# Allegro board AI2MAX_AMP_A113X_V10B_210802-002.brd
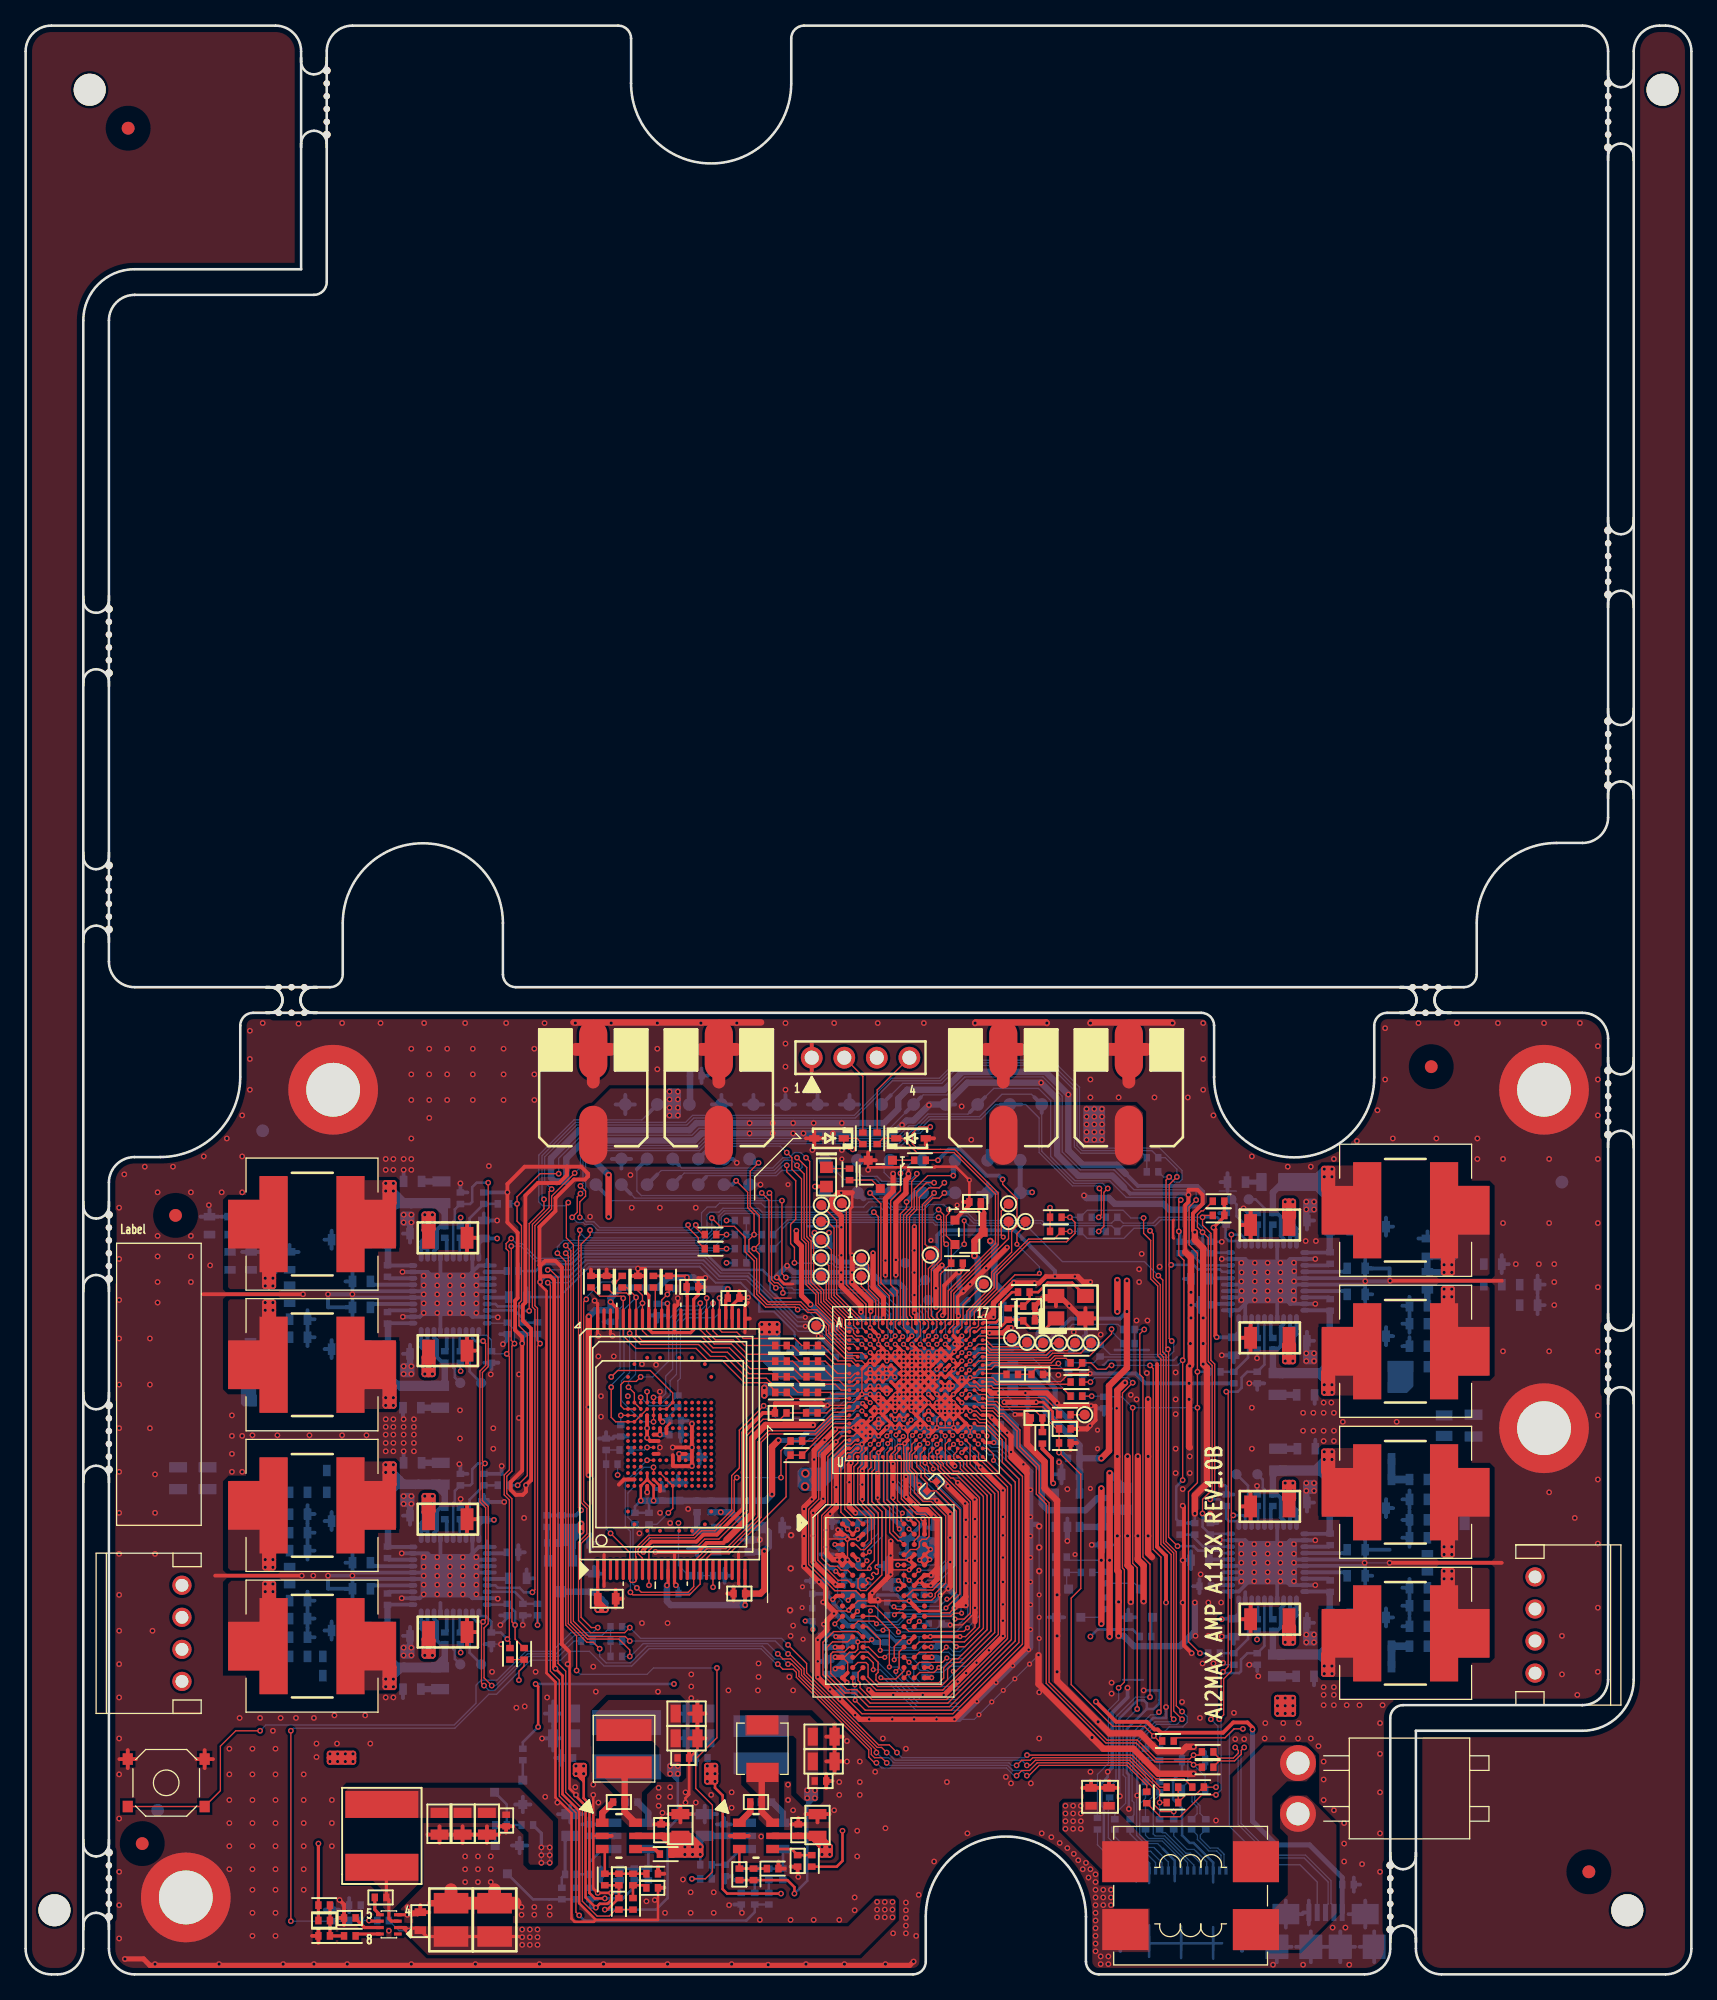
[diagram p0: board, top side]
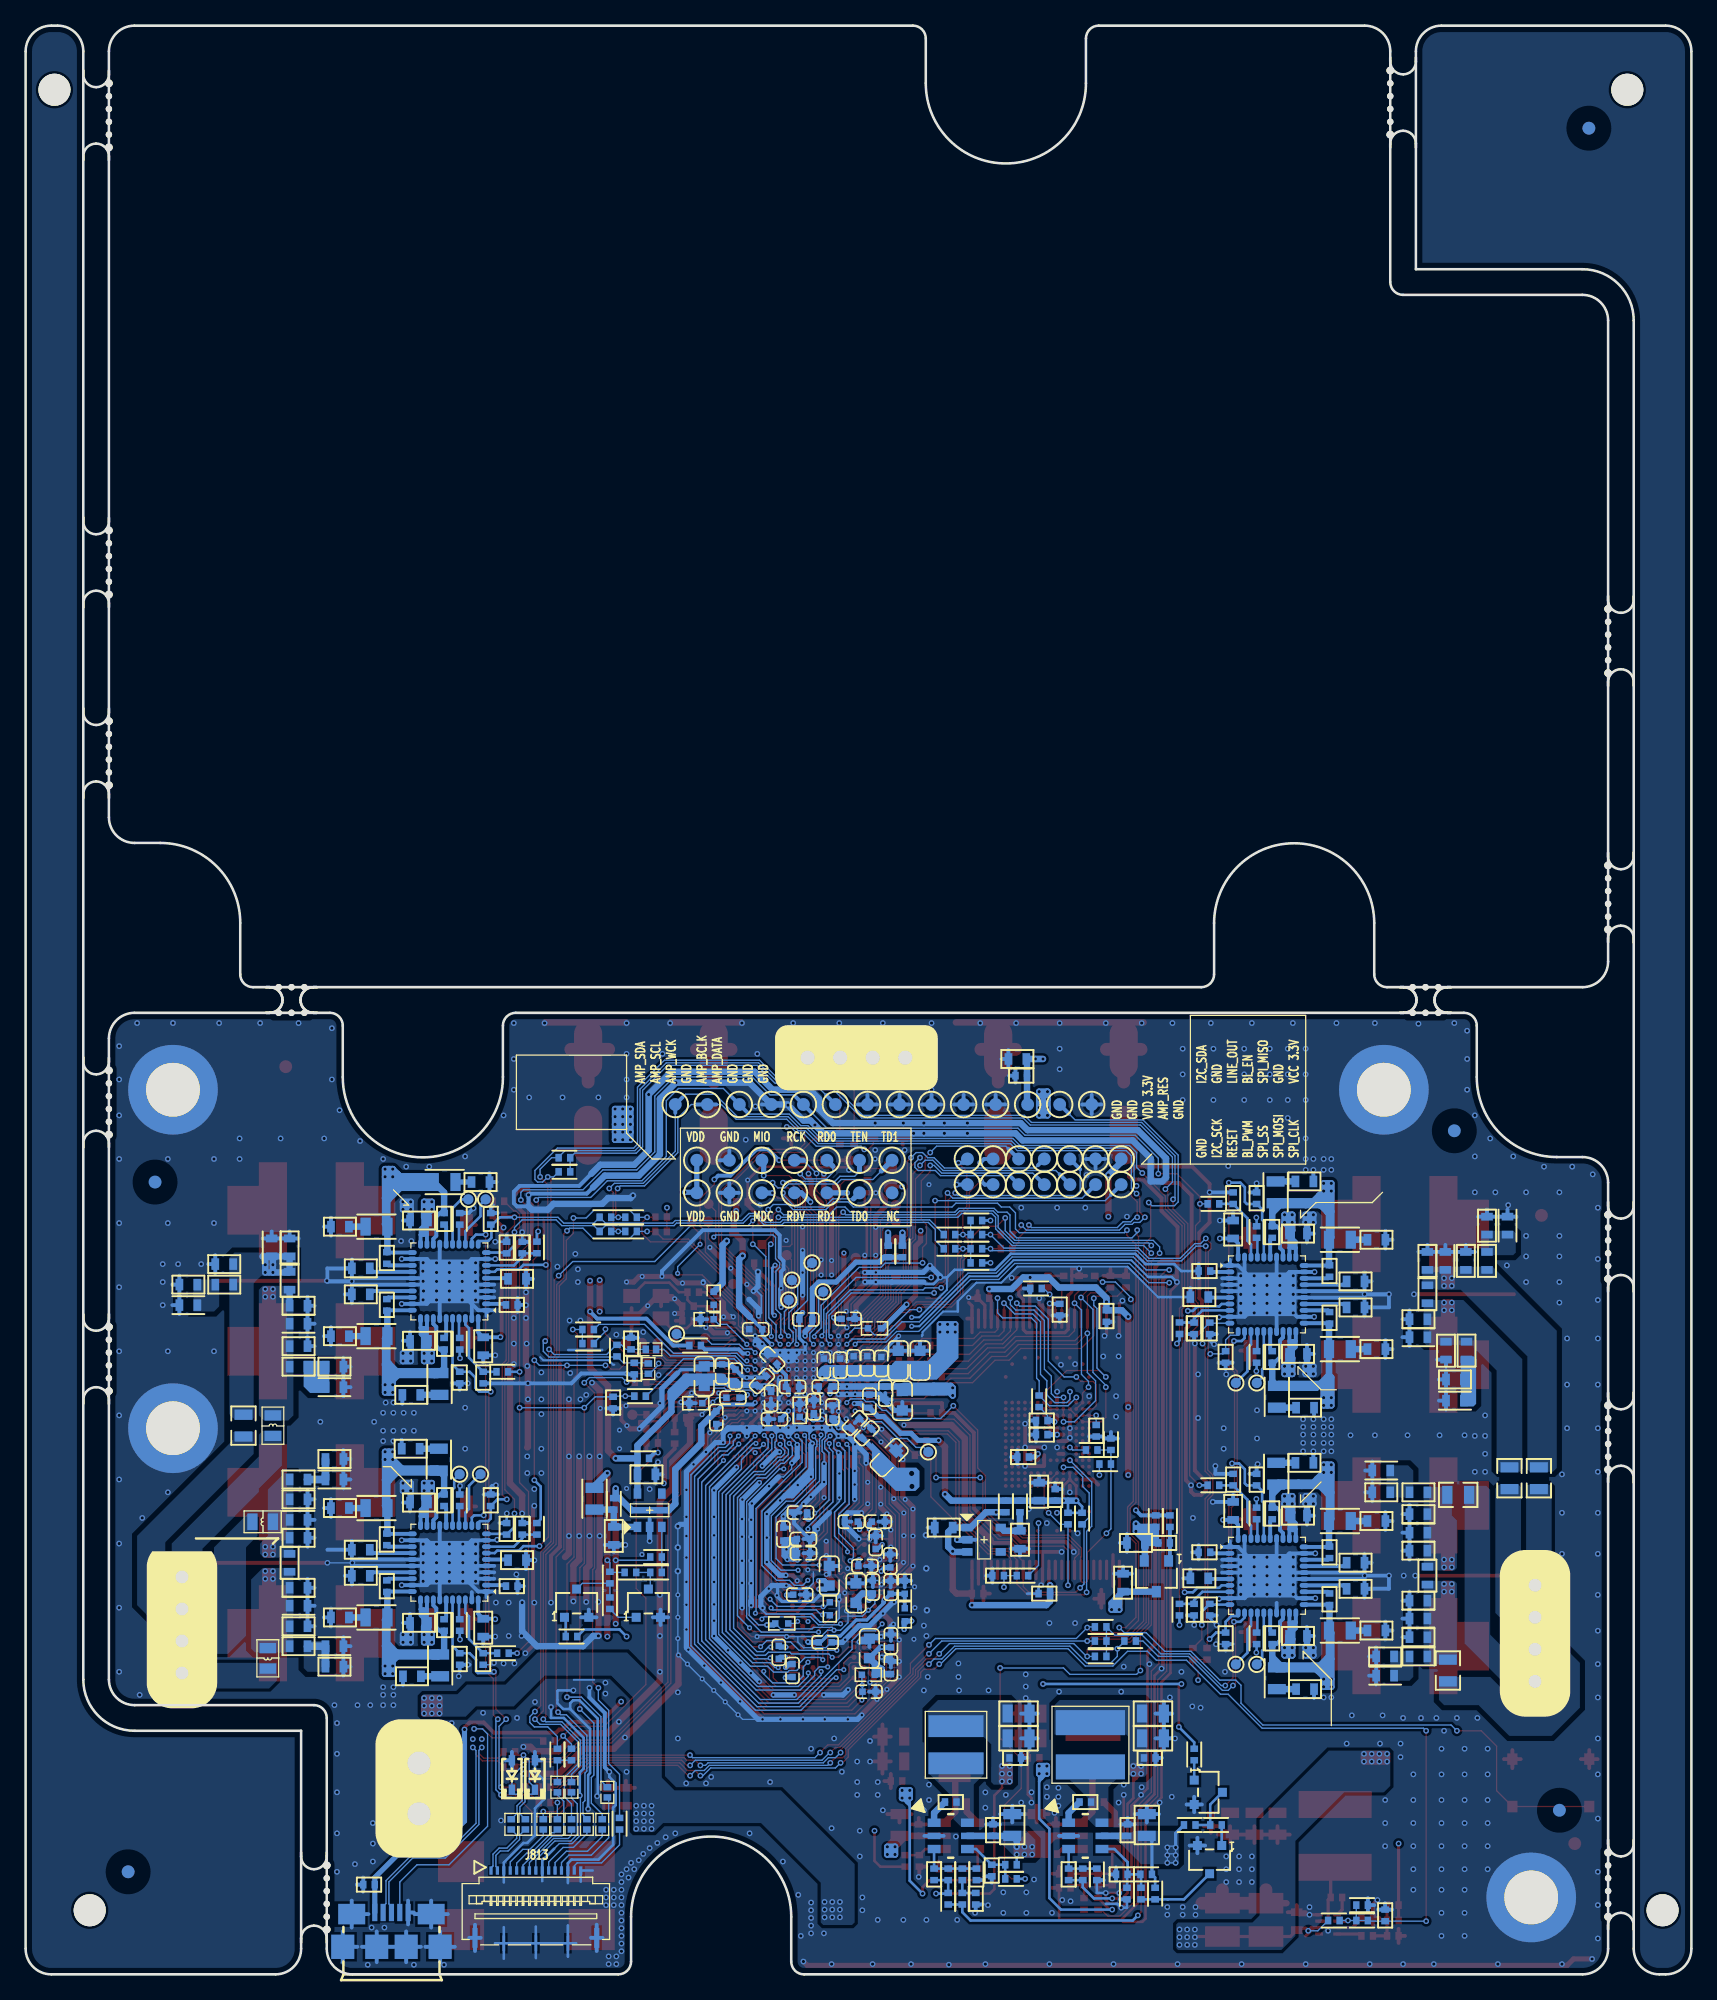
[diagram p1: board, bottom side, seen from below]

Outline 130 x 152 mm; copper layers: TOP, MID1(L2), MID2(L3), BOTTOM. Coordinates in mm from the lower left corner of the outline.
Outline path: 0,150 0,2 arc(0.59,0.59) 2,0 2.5,0 arc(3.91,0.59) 4.5,2 4.5,129 arc(5.67,131.83) 8.5,133 21.5,133 21.5,150 arc(20.91,151.41) 19.5,152 2,152 arc(0.59,151.41) 0,150 ; 6.5,129 6.5,79 arc(7.09,77.59) 8.5,77 23.75,77 arc(24.46,77.29) 24.75,78 24.75,82 arc(31,88.25) 37.25,82 37.25,78 arc(37.54,77.29) 38.25,77 112.25,77 arc(112.96,77.29) 113.25,78 113.25,82 arc(115.08,86.42) 119.5,88.25 121.5,88.25 arc(122.91,88.84) 123.5,90.25 123.5,150 arc(122.91,151.41) 121.5,152 60.75,152 arc(60.04,151.71) 59.75,151 59.75,147.5 arc(53.5,141.25) 47.25,147.5 47.25,151 arc(46.96,151.71) 46.25,152 25.5,152 arc(24.09,151.41) 23.5,150 23.5,132 arc(23.21,131.29) 22.5,131 8.5,131 arc(7.09,130.41) 6.5,129 ; 6.5,61.75 6.5,2 arc(7.09,0.59) 8.5,0 69.25,0 arc(69.96,0.29) 70.25,1 70.25,4.5 arc(76.5,10.75) 82.75,4.5 82.75,1 arc(83.04,0.29) 83.75,0 104.5,0 arc(105.91,0.59) 106.5,2 106.5,20 arc(106.79,20.71) 107.5,21 121.5,21 arc(122.91,21.59) 123.5,23 123.5,73 arc(122.91,74.41) 121.5,75 106.25,75 arc(105.54,74.71) 105.25,74 105.25,70 arc(99,63.75) 92.75,70 92.75,74 arc(92.46,74.71) 91.75,75 17.75,75 arc(17.04,74.71) 16.75,74 16.75,70 arc(14.92,65.58) 10.5,63.75 8.5,63.75 arc(7.09,63.16) 6.5,61.75 ; 108.5,19 108.5,2 arc(109.09,0.59) 110.5,0 128,0 arc(129.41,0.59) 130,2 130,150 arc(129.41,151.41) 128,152 127.5,152 arc(126.09,151.41) 125.5,150 125.5,23 arc(124.33,20.17) 121.5,19 108.5,19

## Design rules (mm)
net group I2S1: nets BCLK DATA LRCK
net group POWER: nets N21714583 N21714673 N21714779 N21715058 N21715192 N21715315 N21715441 N21715523 N21715623 N21715900 N21716032 N21716155 N21722582 N21722669 N21722769 N21723040 N21723161 N21723285 N21723494 N21723601 N21723713 N21724007 N21727322 N21727332
net group USBOTG_A_DM: nets N21775203 N22017810 USBOTG_A_DM
net group USBOTG_A_DP: nets N21775223 N22060831 USBOTG_A_DP

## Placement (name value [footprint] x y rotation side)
C1  105P/50V/1608  [C1608]  84.55 13.85 90 top
C2  104P/50V/1608  [C1608]  83.15 13.85 90 top
C3  106P/50V/3225  [C3225]  36.6 4.25 90 top
C4  104P/50V/1608  [C1608]  30.8 4.15 90 top
C5  104P/16V/1005  [C1005]  27.7 6 0 top
C6  226P/10V/2012  [C2012]  32.3 11.75 270 top
C7  226P/10V/2012  [C2012]  34.1 11.75 270 top
C8  OPEN-226P/10V/2012  [C2012]  36 11.75 270 top
C9  104P/16V/1005  [C1005]  37.5 12 90 top
C10  470P/50V/1005  [C1005]  23.3 4.2 180 top
C11  223P/50V/1005  [C1005]  25.3 4.4 0 top
C12  OPEN-104P/16V/1005  [C1005]  23.9 4.6 270 bottom
C13  226P/10V/2012  [C2012]  42.5 11.65 90 bottom
C14  104P/16V/1005  [C1005]  44 11.25 270 bottom
C15  104P/16V/1005  [C1005]  47.3 13.44 180 bottom
C16  226P/6.3V/2012  [C2012]  42.02 20.34 180 bottom
C17  104P/16V/1005  [C1005]  42.27 16.88 0 bottom
C18  226P/6.3V/2012  [C2012]  42.02 18.41 180 bottom
C19  330P/50V/1005  [C1005]  48.6 7.8 270 bottom
C20  104P/16V/1005  [C1005]  44.45 7.8 180 bottom
C21  106P/6.3V/1608  [C1608]  43.35 33.65 0 bottom
C22  106P/6.3V/1608  [C1608]  44.35 30.55 90 bottom
C23  104P/16V/1005  [C1005]  41.15 33.65 0 bottom
C30  106P/50V/3225  [C3225]  33.2 4.25 90 top
C51  226P/10V/2012  [C2012]  53 11.65 90 bottom
C52  104P/16V/1005  [C1005]  54.5 11.25 270 bottom
C53  104P/16V/1005  [C1005]  57.8 13.44 180 bottom
C54  226P/6.3V/2012  [C2012]  52.51 20.34 180 bottom
C55  104P/16V/1005  [C1005]  52.77 16.88 0 bottom
C56  226P/6.3V/2012  [C2012]  52.51 18.41 180 bottom
C57  226P/10V/2012  [C2012]  51.1 11.65 90 top
C58  104P/16V/1005  [C1005]  49.6 11.25 270 top
C59  104P/16V/1005  [C1005]  46.3 13.44 0 top
C60  226P/6.3V/2012  [C2012]  51.58 20.34 0 top
C61  104P/16V/1005  [C1005]  51.33 16.88 180 top
C62  226P/6.3V/2012  [C2012]  51.58 18.41 0 top
C63  270P/50V/1005  [C1005]  59.1 7.8 270 bottom
C64  270P/50V/1005  [C1005]  46.3 7.4 270 top
C65  104P/16V/1005  [C1005]  54.6 8.1 90 bottom
C66  102P/16V/1005  [C1005]  55.85 5.9 90 bottom
C67  102P/16V/1005  [C1005]  48.9 6.75 180 top
C68  226P/10V/2012  [C2012]  61.8 11.65 90 top
C69  104P/16V/1005  [C1005]  60.3 11.25 270 top
C70  104P/16V/1005  [C1005]  57 13.44 0 top
C71  226P/6.3V/2012  [C2012]  62.28 18.54 0 top
C72  104P/16V/1005  [C1005]  62.03 15.08 180 top
C73  226P/6.3V/2012  [C2012]  62.28 16.61 0 top
C74  330P/50V/1005  [C1005]  55.7 7.8 270 top
C75  OPEN-104P/16V/1005  [C1005]  60.25 8.85 90 top
C76  106P/6.3V/1608  [C1608]  81.55 39 180 bottom
C77  OPEN-106P/6.3V/1608  [C1608]  52.4 33.9 270 bottom
C78  472P/50V/1608  [C1608]  84.1 34.2 270 bottom
C79  OPEN-472P/50V/1608  [C1608]  58.35 34.85 0 bottom
C101  104P/16V/1005  [C0402]  76.1 43.43 90 bottom
C102  105P/6.3V/1005  [C0402]  69.11 51.08 180 bottom
C103  OPEN-150P/50V/1005  [C1005]  84.15 44.6 90 bottom
C104  OPEN-150P/50V/1005  [C1005]  78.95 46.8 180 top
C105  OPEN-150P/50V/1005  [C1005]  82.5 47.25 90 bottom
C106  OPEN-150P/50V/1005  [C1005]  82.75 49.2 270 bottom
C201  105P/6.3V/1608  [C1608]  94.29 48.99 270 bottom
C202  223P/16V/1005  [C1005]  97.34 49.19 270 bottom
C203  271P/50V/1608  [C1608]  99.9 45.2 180 bottom
C204  104P/16V/1005  [C1005]  96.12 46.55 90 bottom
C205  100uF/35V/CLZ  [ECAP_8PI_H10]  54.1 68.8 270 top
C206  104P/50V/1608  [C1608]  99.3 49.42 0 bottom
C207  271P/50V/1608  [C1608]  105.47 49.78 180 bottom
C208  OPEN-104P/16V/1005  [C1005]  92.06 52.22 0 bottom
C209  105P/50V/1608  [C1608]  108.7 52.15 180 bottom
C210  223P/16V/1005  [C1005]  101.81 52.22 90 bottom
C211  105P/16V/1608  [C1608]  103.84 53.04 0 bottom
C213  471P/50V/1608  [C1608]  109.4 54.1 90 bottom
C214  105P/16V/1608  [C1608]  103.84 55.07 0 bottom
C215  223P/16V/1005  [C1005]  101.81 55.88 270 bottom
C216  105P/50V/1608  [C1608]  109.4 56.7 270 bottom
C217  330P/50V/1005  [C1005]  92.46 56.69 270 bottom
C218  105P/6.3V/1608  [C1608]  91.65 54.25 180 bottom
C219  271P/50V/1608  [C1608]  105.47 58.32 180 bottom
C220  223P/16V/1005  [C1005]  97.34 58.93 270 bottom
C221  271P/50V/1608  [C1608]  94.5 61.8 0 bottom
C222  330P/50V/1005  [C1005]  93.7 58.93 270 bottom
C223  100uF/35V/CLZ  [ECAP_8PI_H10]  44.3 68.8 270 top
C224  104P/50V/1608  [C1608]  99.3 58.8 0 bottom
C225  223P/16V/1005  [C1005]  97.34 27.25 270 bottom
C226  104P/16V/1005  [C1005]  96.12 24.6 90 bottom
C228  271P/50V/1608  [C1608]  99.85 23.25 180 bottom
C229  271P/50V/1608  [C1608]  105.47 27.84 180 bottom
C230  105P/6.3V/1608  [C1608]  94.29 27.04 270 bottom
C231  104P/50V/1608  [C1608]  99.3 27.42 0 bottom
C232  OPEN-104P/16V/1005  [C1005]  92.06 30.28 0 bottom
C233  105P/50V/1608  [C1608]  108.7 30.15 180 bottom
C234  223P/16V/1005  [C1005]  101.81 30.28 90 bottom
C235  105P/16V/1608  [C1608]  103.84 31.09 0 bottom
C237  471P/50V/1608  [C1608]  109.4 32.1 90 bottom
C238  105P/16V/1608  [C1608]  103.84 33.12 0 bottom
C239  223P/16V/1005  [C1005]  101.81 33.93 270 bottom
C240  105P/50V/1608  [C1608]  108.7 34.05 0 bottom
C241  330P/50V/1005  [C1005]  92.46 34.75 270 bottom
C242  105P/6.3V/1608  [C1608]  91.65 32.31 180 bottom
C243  271P/50V/1608  [C1608]  105.47 36.37 180 bottom
C244  223P/16V/1005  [C1005]  97.34 36.98 270 bottom
C245  271P/50V/1608  [C1608]  99.95 41 180 bottom
C246  330P/50V/1005  [C1005]  93.7 36.98 270 bottom
C248  104P/50V/1608  [C1608]  99.3 36.8 0 bottom
C249  OPEN-105P/6.3V/1608  [C1608]  52.6 71.4 0 bottom
C250  OPEN-104P/16V/1005  [C1005]  52.3 70.1 180 bottom
C251  OPEN-330P/50V/1005  [C1005]  94.29 46.55 90 bottom
C252  OPEN-330P/50V/1005  [C1005]  91.24 56.69 270 bottom
C253  OPEN-330P/50V/1005  [C1005]  94.29 24.6 90 bottom
C254  OPEN-330P/50V/1005  [C1005]  91.24 34.75 270 bottom
C255  106P/35V/3216  [C3216]  97.1 49.65 180 top
C256  106P/35V/3216  [C3216]  97.1 58.45 180 top
C257  106P/35V/3216  [C3216]  97.1 27.7 180 top
C258  106P/35V/3216  [C3216]  97.1 36.5 180 top
C259  121\P/50V/1608  [C1608]  108.7 49 0 bottom
C260  121\P/50V/1608  [C1608]  114.5 55.4 0 bottom
C261  121\P/50V/1608  [C1608]  108.7 27.15 0 bottom
C262  121\P/50V/1608  [C1608]  108.7 37.05 180 bottom
C263  OPEN-224P/50V/1608  [C1608]  108.7 47.4 180 bottom
C264  OPEN-224P/50V/1608  [C1608]  105.9 47.4 180 bottom
C265  OPEN-224P/50V/1608  [C1608]  117.3 53.8 180 bottom
C266  OPEN-224P/50V/1608  [C1608]  114.5 53.8 180 bottom
C267  OPEN-224P/50V/1608  [C1608]  108.7 25.6 180 bottom
C268  OPEN-224P/50V/1608  [C1608]  105.9 24 180 bottom
C269  OPEN-224P/50V/1608  [C1608]  105.9 40.2 0 bottom
C270  OPEN-224P/50V/1608  [C1608]  108.7 38.6 0 bottom
C301  105P/6.3V/1608  [C1608]  35.76 36.15 90 bottom
C302  223P/16V/1005  [C1005]  32.71 35.95 90 bottom
C303  271P/50V/1608  [C1608]  30.2 39.9 0 bottom
C304  104P/16V/1005  [C1005]  33.93 38.59 270 bottom
C305  100uF/35V/CLZ  [ECAP_8PI_H10]  76.3 68.8 270 top
C306  104P/50V/1608  [C1608]  30.7 35.78 180 bottom
C307  271P/50V/1608  [C1608]  24.58 35.36 0 bottom
C308  OPEN-104P/16V/1005  [C1005]  38 32.92 180 bottom
C309  105P/50V/1608  [C1608]  21.3 33.05 0 bottom
C310  223P/16V/1005  [C1005]  28.24 32.92 270 bottom
C311  105P/16V/1608  [C1608]  26.21 32.11 180 bottom
C313  471P/50V/1608  [C1608]  20.6 31.1 270 bottom
C314  105P/16V/1608  [C1608]  26.21 30.07 180 bottom
C315  223P/16V/1005  [C1005]  28.24 29.26 90 bottom
C316  105P/50V/1608  [C1608]  21.3 29.15 180 bottom
C317  330P/50V/1005  [C1005]  37.59 28.45 90 bottom
C318  105P/6.3V/1608  [C1608]  38.4 30.89 0 bottom
C319  271P/50V/1608  [C1608]  24.58 26.82 0 bottom
C320  223P/16V/1005  [C1005]  32.71 26.21 90 bottom
C321  271P/50V/1608  [C1608]  30.15 22.25 0 bottom
C322  330P/50V/1005  [C1005]  36.35 26.21 90 bottom
C323  100uF/35V/CLZ  [ECAP_8PI_H10]  86.1 68.8 270 top
C324  104P/50V/1608  [C1608]  30.7 26.4 180 bottom
C325  223P/16V/1005  [C1005]  32.71 57.9 90 bottom
C326  104P/16V/1005  [C1005]  33.93 60.54 270 bottom
C328  271P/50V/1608  [C1608]  30.2 61.85 0 bottom
C329  271P/50V/1608  [C1608]  24.58 57.3 0 bottom
C330  105P/6.3V/1608  [C1608]  35.76 58.1 90 bottom
C331  104P/50V/1608  [C1608]  30.7 57.78 180 bottom
C332  OPEN-104P/16V/1005  [C1005]  38 54.86 180 bottom
C333  105P/50V/1608  [C1608]  20.6 55.65 90 bottom
C334  223P/16V/1005  [C1005]  28.24 54.86 270 bottom
C335  105P/16V/1608  [C1608]  26.21 54.05 180 bottom
C337  471P/50V/1608  [C1608]  20.6 53.05 270 bottom
C338  105P/16V/1608  [C1608]  26.21 52.02 180 bottom
C339  223P/16V/1005  [C1005]  28.24 51.21 90 bottom
C340  105P/50V/1608  [C1608]  21.3 51.1 180 bottom
C341  330P/50V/1005  [C1005]  37.59 50.39 90 bottom
C342  105P/6.3V/1608  [C1608]  38.4 52.83 0 bottom
C343  271P/50V/1608  [C1608]  24.58 48.77 0 bottom
C344  223P/16V/1005  [C1005]  32.71 48.16 90 bottom
C345  271P/50V/1608  [C1608]  30.15 44.2 0 bottom
C346  330P/50V/1005  [C1005]  36.35 48.16 90 bottom
C348  104P/50V/1608  [C1608]  30.7 48.4 180 bottom
C349  OPEN-330P/50V/1005  [C1005]  35.76 38.59 270 bottom
C350  OPEN-330P/50V/1005  [C1005]  38.81 28.45 90 bottom
C351  OPEN-330P/50V/1005  [C1005]  35.76 60.54 270 bottom
C352  OPEN-330P/50V/1005  [C1005]  38.81 50.39 90 bottom
C353  106P/35V/3216  [C3216]  32.95 35.5 0 top
C354  106P/35V/3216  [C3216]  32.95 26.7 0 top
C355  106P/35V/3216  [C3216]  32.95 57.45 0 top
C356  106P/35V/3216  [C3216]  32.95 48.65 0 top
C357  121\P/50V/1608  [C1608]  21.3 35.9 180 bottom
C358  121\P/50V/1608  [C1608]  21.3 26.3 0 bottom
C359  121\P/50V/1608  [C1608]  17.6 55.65 270 bottom
C360  121\P/50V/1608  [C1608]  19.15 48.65 270 bottom
C361  OPEN-224P/50V/1608  [C1608]  21.3 37.6 0 bottom
C362  OPEN-224P/50V/1608  [C1608]  24.2 37.6 0 bottom
C363  OPEN-224P/50V/1608  [C1608]  23.9 24.8 180 bottom
C364  OPEN-224P/50V/1608  [C1608]  21.3 24.8 180 bottom
C365  OPEN-224P/50V/1608  [C1608]  15.95 55.65 90 bottom
C366  OPEN-224P/50V/1608  [C1608]  15.95 58.4 90 bottom
C367  OPEN-224P/50V/1608  [C1608]  18.45 46.4 180 bottom
C368  OPEN-224P/50V/1608  [C1608]  17.55 48.65 90 bottom
FB201  CIS21J121NE  [CIS2012]  113 42.8 90 bottom
FB202  120ohm/5A/2012  [BLM21]  110.7 42.8 90 bottom
FB203  120ohm/5A/2012  [BLM21]  111.1 24.65 270 bottom
FB204  120ohm/5A/2012  [BLM21]  111.5 35.3 0 bottom
FB301  CIS21J121NE  [CIS2012]  19 23.7 90 bottom
FB302  CIS21J121NE  [CIS2012]  18.2 37.4 0 bottom
FB303  CIS21J121NE  [CIS2012]  11.9 38.7 270 bottom
FB304  CIS21J121NE  [CIS2012]  14.2 38.7 270 bottom
J803  S4B-EH(LF)(SN)  [SXB-EH-4P]  121.5 27.25 270 top
J804  S4B-EH(LF)(SN)  [SXB-EH-4P]  8.5 26.6 90 top
J812  -  [51318-0023L-001]  106.5 14.5 270 top
J813  FH41-15S-0.5SH(05)  [FH41-15S-0_5SH]  90.18 4.9 0 bottom
J814  10118192-0002LF  [MICRO_USB_10118192]  101.45 2.5 180 bottom
L1  SWPA6045S6R8MT  [SWPA6045S]  27.8 10.8 0 top
L2  MLPS-5035-4R7M-E-EH  [COIL_MLPS5035]  46.9 17.91 0 bottom
L51  LVS404018-2R2M  [COIL_LVS404018]  57.39 17.91 0 bottom
L52  LVS404018-2R2M  [COIL_LVS404018]  46.7 17.6 180 top
L53  SMPI0402BW-3R3M  [COIL_SMPI0402BW]  57.5 17.6 90 top
L201  SPH10040-100M  [COIL_SPH10040]  107.7 48.6 0 top
L202  SPH10040-100M  [COIL_SPH10040]  107.7 59.6 0 top
L203  SPH10040-100M  [COIL_SPH10040]  107.7 26.6 0 top
L204  SPH10040-100M  [COIL_SPH10040]  107.7 37.6 0 top
L211  OPEN-SWPA8065S100NT  [SWPA8065S]  107.7 48.6 90 top
L212  OPEN-SWPA8065S100NT  [SWPA8065S]  107.7 59.6 90 top
L213  OPEN-SWPA8065S100NT  [SWPA8065S]  107.7 26.6 90 top
L214  OPEN-SWPA8065S100NT  [SWPA8065S]  107.7 37.6 90 top
L301  SPH10040-100M  [COIL_SPH10040]  22.35 36.58 180 top
L302  SPH10040-100M  [COIL_SPH10040]  22.35 25.6 180 top
L303  SPH10040-100M  [COIL_SPH10040]  22.35 58.52 180 top
L304  SPH10040-100M  [COIL_SPH10040]  22.35 47.55 180 top
L311  OPEN-SWPA8065S100NT  [SWPA8065S]  22.35 36.58 270 top
L312  OPEN-SWPA8065S100NT  [SWPA8065S]  22.35 25.6 270 top
L313  OPEN-SWPA8065S100NT  [SWPA8065S]  22.35 58.52 270 top
L314  OPEN-SWPA8065S100NT  [SWPA8065S]  22.35 47.55 270 top
NOREF  -  [unnamed]  123.5 95.25 90 top
NOREF#2  -  [unnamed#2]  12.5 6 0 top
NOREF#3  -  [#3]  78.11 -71 90 top
NOREF#4  -  [unnamed#2]  118.5 42.6 0 top
NOREF#5  -  [unnamed#2]  9.1 10.2 0 top
NOREF#6  -  [#3]  -55.5 -9.75 90 top
NOREF#7  -  [#3]  -13.5 -16 0 top
NOREF#8  -  [unnamed#2]  109.7 70.8 0 top
NOREF#9  -  [#3]  146.5 -32 90 top
NOREF#10  -  [#3]  -55.5 -71 90 top
NOREF#11  -  [unnamed#2]  122 8 0 top
NOREF#12  -  [unnamed#4]  20.75 75 180 top
NOREF#13  -  [#3]  6.5 -2 0 top
NOREF#14  -  [unnamed]  6.5 84 270 top
NOREF#15  -  [#3]  -55.5 -71 0 top
NOREF#16  -  [unnamed#5]  127.75 147 0 top
NOREF#17  -  [unnamed#4]  20.75 77 0 top
NOREF#18  -  [#3]  -55.5 5.45 0 top
NOREF#19  -  [unnamed#5]  5 147 0 top
NOREF#20  -  [unnamed]  6.5 104 270 top
NOREF#21  -  [unnamed]  123.5 145 90 top
NOREF#22  -  [unnamed]  6.5 7 270 top
NOREF#23  -  [unnamed#4]  109.25 75 180 top
NOREF#24  -  [unnamed#5]  2.25 5 0 top
NOREF#25  -  [unnamed#2]  11.7 59.2 0 top
NOREF#26  -  [#3]  -55.5 -41.75 90 top
NOREF#27  -  [#3]  2 0 90 top
NOREF#28  -  [#3]  0 150 0 top
NOREF#29  -  [unnamed]  23.5 146 270 top
NOREF#30  -  [unnamed]  106.5 6 90 top
NOREF#31  -  [unnamed#2]  8 144 0 top
NOREF#32  -  [#3]  6.5 -14 90 top
NOREF#33  -  [#3]  141.5 -81 90 top
NOREF#34  -  [unnamed]  6.5 41.88 270 top
NOREF#35  -  [#3]  146.5 -71 90 top
NOREF#36  -  [unnamed]  123.5 48 90 top
NOREF#37  -  [#3]  141.5 -81 90 top
NOREF#38  -  [#3]  -55.5 80 0 top
NOREF#39  -  [unnamed]  123.5 110.13 90 top
NOREF#40  -  [#3]  6.5 44.01 0 top
NOREF#41  -  [unnamed]  123.5 68 90 top
NOREF#42  -  [#3]  70.25 0 90 top
NOREF#43  -  [unnamed#4]  109.25 77 0 top
NOREF#44  -  [#3]  -55.5 -41.75 0 top
NOREF#45  -  [unnamed#5]  125 5 0 top
NOREF#46  -  [unnamed#2]  24 69 0 top
NOREF#47  -  [unnamed]  6.5 56.75 270 top
NOREF#48  -  [unnamed#2]  118.5 69 0 top
NOREF#49  -  [unnamed#2]  18.5 65.8 180 bottom
NOREF#50  -  [unnamed#2]  10.3 12.8 180 bottom
NOREF#51  -  [unnamed#2]  8 144 180 bottom
NOREF#52  -  [unnamed#2]  122 8 180 bottom
NOREF#53  -  [unnamed#2]  119.9 61.8 180 bottom
Q1  WPM3401  [SOT23_LRT_W2_7_WPM3401]  41.75 31.05 0 bottom
Q2  OPEN-MMBT3904  [SOT23_LRT_MMBT3904]  37.6 8.95 0 bottom
Q3  OPEN-MMBT3904  [SOT23_LRT_MMBT3904]  37.7 14.2 270 bottom
Q4  MMBT3904  [SOT23_LRT_MMBT3904]  87 28.95 180 bottom
Q5  MMBT3904  [SOT23_LRT_MMBT3904]  81.4 28.95 180 bottom
R1  OPEN-204/F/1005  [R1005]  27.9 4.2 0 bottom
R2  OPEN-000/1005  [R1005]  25.7 4.2 180 bottom
R3  4992/F/1005  [R1005]  25.7 5.4 0 bottom
R6  104/1005  [R1005]  42.55 7.8 180 bottom
R7  OPEN-473/1005  [R1005]  44.05 6.3 90 bottom
R8  104/F/1005  [R1005]  47.5 7.8 270 bottom
R9  2212/F/1005  [R1005]  46.4 7.8 90 bottom
R10  364/F/1005  [R1005]  23.3 5.4 180 top
R11  4022/F/1005  [R1005]  23.3 3 0 top
R12  OPEN-103/1005  [R1005]  41.8 35.35 270 bottom
R13  472/1005  [R1005]  40.7 35.35 270 bottom
R15  OPEN-103/1005  [R1005]  38.8 17.15 90 bottom
R16  OPEN-103/1005  [R1005]  37.1 11.65 0 bottom
R17  OPEN-103/1005  [R1005]  39.15 11.65 180 bottom
R18  OPEN-103/1005  [R1005]  41.85 6.3 270 bottom
R19  OPEN-000/1005  [R1005]  42.95 6.3 270 bottom
R20  103/F/1005  [R1005]  25.3 3 180 top
R51  104/F/1005  [R1005]  58 7.8 270 bottom
R52  472/1005  [R1005]  49.95 9.38 0 top
R53  124/F/1005  [R1005]  45.2 7.4 270 top
R54  472/1005  [R1005]  53.1 7.45 0 bottom
R55  105/F/1005  [R1005]  56.9 7.8 270 bottom
R56  104/F/1005  [R1005]  56.9 5.9 270 bottom
R57  125/F/1005  [R1005]  47.4 7.4 270 top
R58  124/F/1005  [R1005]  47.4 5.5 270 top
R59  1213/F/1005  [R1005]  55.8 7.8 90 bottom
R60  1623/F/1005  [R1005]  48.9 7.85 180 top
R61  124/F/1005  [R1005]  56.8 7.8 270 top
R62  102/1005  [R1005]  61.35 8.85 90 top
R63  9532/F/1005  [R1005]  58.3 8.25 180 top
R101  OPEN-000/1005  [R1005]  81.1 43.65 0 top
R102  OPEN-330/1005  [R1005]  82 46.2 0 top
R103  101/1005  [R1005]  86.1 49.2 0 bottom
R104  101/1005  [R1005]  86.1 50.3 0 bottom
R105  000/1005  [R1005]  62.68 56.39 270 bottom
R106  OPEN-000/1005  [R1005]  61.57 56.39 270 bottom
R107  101/1005  [R1005]  82 45.1 0 top
R108  101/1005  [R1005]  77 46.8 0 top
R109  BLM15PD121SN1D  [BLM15]  81.4 47.25 90 bottom
R110  BLM15PD121SN1D  [BLM15]  81.2 48.75 0 bottom
R201  472/1005  [R1005]  96.12 49.19 270 bottom
R202  6R8/F/2012  [R2012]  97.7 46.05 90 bottom
R203  6R8/F/2012  [R2012]  102.62 49.78 0 bottom
R204  472/F/1608  [R1608]  108.7 50.75 0 bottom
R205  472/F/1608  [R1608]  110.8 56.7 90 bottom
R206  6R8/F/2012  [R2012]  102.62 58.32 180 bottom
R207  472/1005  [R1005]  96.12 58.93 270 bottom
R208  6R8/F/2012  [R2012]  97.3 61.8 180 bottom
R209  000/1005  [R1005]  82.75 59.05 0 bottom
R210  000/1005  [R1005]  82.75 57.95 0 bottom
R211  OPEN-101/1005  [R1005]  57.9 57.7 0 bottom
R212  OPEN-101/1005  [R1005]  57.9 56.6 0 bottom
R213  6R8/F/2012  [R2012]  97.65 24.1 90 bottom
R214  472/1005  [R1005]  96.12 27.25 270 bottom
R215  101/1005  [R1005]  89.5 13.4 0 top
R216  OPEN-101/1005  [R1005]  89.5 14.6 0 top
R217  6R8/F/2012  [R2012]  102.62 27.84 0 bottom
R219  OPEN-101/1005  [R1005]  87.5 13.8 270 top
R220  472/F/1608  [R1608]  108.7 28.75 0 bottom
R221  472/F/1608  [R1608]  108.7 35.45 180 bottom
R222  6R8/F/2012  [R2012]  102.62 36.37 180 bottom
R223  472/1005  [R1005]  96.12 36.98 270 bottom
R224  6R8/F/2012  [R2012]  97.75 40.15 90 bottom
R225  OPEN-101/1005  [R1005]  87.95 63.7 0 bottom
R226  OPEN-101/1005  [R1005]  87.95 62.6 0 bottom
R227  101/1005  [R1005]  92.8 47 0 bottom
R228  101/1005  [R1005]  90.1 56.7 270 bottom
R229  101/1005  [R1005]  92.75 25.05 0 bottom
R230  101/1005  [R1005]  90.1 34.75 270 bottom
R231  OPEN-330/1005  [R1005]  83.85 48.65 270 bottom
R233  OPEN-100/F/1608  [R1608]  105.9 45.8 0 bottom
R234  OPEN-100/F/1608  [R1608]  117.3 52.2 0 bottom
R235  OPEN-100/F/1608  [R1608]  105.9 25.6 0 bottom
R236  OPEN-100/F/1608  [R1608]  105.9 38.6 180 bottom
R238  101/1005  [R1005]  84.75 59.05 0 bottom
R239  101/1005  [R1005]  84.75 57.95 0 bottom
R240  OPEN-101/1005  [R1005]  91.5 14.6 0 top
R301  472/1005  [R1005]  33.93 35.95 90 bottom
R302  6R8/F/2012  [R2012]  32.4 39.05 270 bottom
R303  6R8/F/2012  [R2012]  27.43 35.36 180 bottom
R304  472/F/1608  [R1608]  21.3 34.45 180 bottom
R305  472/F/1608  [R1608]  21.3 27.75 0 bottom
R306  6R8/F/2012  [R2012]  27.43 26.82 0 bottom
R307  472/1005  [R1005]  33.93 26.21 90 bottom
R308  6R8/F/2012  [R2012]  32.35 23.1 270 bottom
R309  101/1005  [R1005]  53.45 57.7 0 top
R310  101/1005  [R1005]  53.45 56.6 0 top
R311  OPEN-101/1005  [R1005]  55.8 57.7 180 bottom
R312  OPEN-101/1005  [R1005]  55.8 56.6 180 bottom
R313  6R8/F/2012  [R2012]  32.45 61 270 bottom
R314  472/1005  [R1005]  33.93 57.9 90 bottom
R315  101/1005  [R1005]  46.1 26 180 bottom
R316  OPEN-101/1005  [R1005]  46.1 24.8 180 bottom
R317  6R8/F/2012  [R2012]  27.43 57.3 180 bottom
R319  472/F/1608  [R1608]  19.2 55.65 270 bottom
R320  OPEN-101/1005  [R1005]  43.8 26 180 bottom
R321  472/F/1608  [R1608]  21.3 49.7 0 bottom
R322  6R8/F/2012  [R2012]  27.43 48.77 0 bottom
R323  472/1005  [R1005]  33.93 48.16 90 bottom
R324  6R8/F/2012  [R2012]  32.35 45.05 270 bottom
R325  101/1005  [R1005]  37.3 38.15 180 bottom
R326  101/1005  [R1005]  39.95 28.45 90 bottom
R327  101/1005  [R1005]  37.3 60.1 180 bottom
R328  101/1005  [R1005]  39.95 50.4 90 bottom
R329  103/1005  [R1005]  84.4 30.95 270 bottom
R330  103/1005  [R1005]  82.8 31.35 180 bottom
R331  000/1005  [R1005]  80.8 31.35 0 bottom
R332  103/1005  [R1005]  84.4 28.95 90 bottom
R333  103/1005  [R1005]  87.4 26.35 180 bottom
R334  000/2012  [R2012]  85.6 37.1 270 bottom
R335  OPEN-000/1005  [R1005]  84.1 36.7 270 bottom
R336  OPEN-000/1005  [R1005]  80.8 32.55 180 bottom
R337  OPEN-472/1005  [R1005]  53.1 8.55 180 bottom
R338  OPEN-101/1005  [R1005]  46.1 27.1 180 bottom
R339  OPEN-100/F/1608  [R1608]  24.2 39.3 180 bottom
R340  OPEN-100/F/1608  [R1608]  23.9 23.3 0 bottom
R341  OPEN-100/F/1608  [R1608]  14.35 58.4 270 bottom
R342  OPEN-100/F/1608  [R1608]  18.45 44.75 0 bottom
R343  101/1005  [R1005]  82.05 45.1 0 bottom
R344  101/1005  [R1005]  82 47.7 0 top
R348  102/1005  [R1005]  93.1 60.3 180 top
R349  102/1005  [R1005]  93.1 59.2 180 top
R350  102/1005  [R1005]  38.9 25 90 top
R351  102/1005  [R1005]  37.8 25 90 top
T1  BPPM00121190172X0F  [COIL_BPPM00121190]  90.92 6.14 0 top
T101  T_POINT_R_1  [TP0_8PI]  82.65 43.65 0 top
T102  T_POINT_R_1  [TP0_8PI]  81.9 49.25 0 top
T103  T_POINT_R_1  [TP0_8PI]  83.15 49.25 0 top
T104  T_POINT_R_1  [TP0_8PI]  79.4 49.25 0 top
T105  T_POINT_R_1  [TP0_8PI]  80.65 49.25 0 top
T106  T_POINT_R_1  [TP0_8PI]  78.15 49.3 0 top
T107  T_POINT_R_1  [TP0_8PI]  79.2 49.95 180 bottom
T108  T_POINT_R_1  [TP0_8PI]  76.96 49.63 0 top
T109  T_POINT_R_1  [TP0_8PI]  65.22 54.46 0 top
T110  T_POINT_R_1  [TP0_8PI]  65.22 55.88 0 top
T111  T_POINT_R_1  [TP0_8PI]  62.08 57.3 0 top
T112  T_POINT_R_1  [TP0_8PI]  62.08 58.72 0 top
T113  T_POINT_R_1  [TP0_8PI]  63.7 60.15 0 top
T114  T_POINT_R_1  [TP0_8PI]  62.1 60 0 top
T115  T_POINT_R_1  [TP0_8PI]  62.08 55.88 0 top
T116  T_POINT_R_1  [TP0_8PI]  62.08 54.46 0 top
T120  T_POINT_R_1  [TP0_8PI]  70.6 56.1 0 top
T125  T_POINT_R_1  [TP0_8PI]  68.63 55.49 180 bottom
T126  T_POINT_R_1  [TP0_8PI]  67.76 53.24 180 bottom
T127  T_POINT_R_1  [TP0_8PI]  70.45 52.6 180 bottom
T129  T_POINT_R_1  [TP1_0PI]  77.62 60.96 180 bottom
T201  T_POINT_R_1  [TP0_8PI]  94.1 60.45 180 bottom
T202  T_POINT_R_1  [TP0_8PI]  95.45 60.45 180 bottom
T203  T_POINT_R_1  [TP0_8PI]  94.5 39.01 180 bottom
T204  T_POINT_R_1  [TP0_8PI]  96.13 39.01 180 bottom
T301  T_POINT_R_1  [TP0_8PI]  35.55 24.18 0 bottom
T302  T_POINT_R_1  [TP0_8PI]  33.92 24.18 0 bottom
T303  T_POINT_R_1  [TP0_8PI]  35.55 46.13 0 bottom
T304  T_POINT_R_1  [TP0_8PI]  33.92 46.13 0 bottom
T305  T_POINT_R_1  [TP1_0PI]  79.3 67.85 0 bottom
T306  T_POINT_R_1  [TP1_0PI]  76.8 67.85 0 bottom
T307  T_POINT_R_1  [TP1_0PI]  74.3 67.85 0 bottom
T308  T_POINT_R_1  [TP1_0PI]  71.8 67.85 0 bottom
T309  T_POINT_R_1  [TP1_0PI]  69.3 67.85 0 bottom
T310  T_POINT_R_1  [TP1_0PI]  66.8 67.85 0 bottom
T311  T_POINT_R_1  [TP1_0PI]  64.3 67.85 0 bottom
T312  T_POINT_R_1  [TP1_0PI]  61.8 67.85 0 bottom
T313  T_POINT_R_1  [TP1_0PI]  59.3 67.85 0 bottom
T314  T_POINT_R_1  [TP1_0PI]  56.8 67.85 0 bottom
T315  T_POINT_R_1  [TP1_0PI]  54.3 67.85 0 bottom
T316  T_POINT_R_1  [TP1_0PI]  51.8 67.85 0 bottom
T317  T_POINT_R_1  [TP1_0PI]  49.3 67.85 0 bottom
T318  T_POINT_R_1  [TP1_0PI]  46.8 67.85 0 bottom
T319  T_POINT_R_1  [TP1_0PI]  77.62 63.5 180 bottom
T320  T_POINT_R_1  [TP1_0PI]  75.08 60.96 180 bottom
T321  T_POINT_R_1  [TP1_0PI]  75.08 63.5 180 bottom
T322  T_POINT_R_1  [TP1_0PI]  72.54 60.96 180 bottom
T323  T_POINT_R_1  [TP1_0PI]  72.54 63.5 180 bottom
T324  T_POINT_R_1  [TP1_0PI]  70 60.96 180 bottom
T325  T_POINT_R_1  [TP1_0PI]  70 63.5 180 bottom
T326  T_POINT_R_1  [TP1_0PI]  67.46 60.96 180 bottom
T327  T_POINT_R_1  [TP1_0PI]  67.46 63.5 180 bottom
T328  T_POINT_R_1  [TP1_0PI]  64.92 60.96 180 bottom
T329  T_POINT_R_1  [TP1_0PI]  64.92 63.5 180 bottom
T330  T_POINT_R_1  [TP1_0PI]  62.38 60.96 180 bottom
T331  T_POINT_R_1  [TP1_0PI]  62.38 63.5 180 bottom
U1  -  [A113X]  69.49 45.57 0 top
U2  MP2338GTL  [SOT583_MP2338]  28.35 3.9 90 top
U3  TMI3252S  [SOT23-6P_TMI3252S]  47.3 10.8 270 bottom
U51  TMI3252S  [SOT23-6P_TMI3252S]  57.8 10.8 270 bottom
U52  TMI3252S  [SOT23-6P_TMI3252S]  46.3 10.8 270 top
U53  TMI3252S  [SOT23-6P_TMI3252S]  57 10.8 270 top
U54  TMI6050-18  [SOT23-5_TMI6050]  81.3 36.2 180 bottom
U55  OPEN-TMI6050-18  [SOT23-5_TMI6050]  55.2 33.9 270 bottom
U201  WA20-6829B  [QFN40_P0_5_W6_WA20-6829B]  96.93 54.05 0 bottom
U202  WA20-6829B  [QFN40_P0_5_W6_WA20-6829B]  96.93 32.11 0 bottom
U301  WA20-6829B  [QFN40_P0_5_W6_WA20-6829B]  33.12 31.09 180 bottom
U302  WA20-6829B  [QFN40_P0_5_W6_WA20-6829B]  33.12 53.04 180 bottom
UNK1R1  103/F/1005  [R1005]  58 5.9 90 bottom
UNK1R2  103/F/1005  [R1005]  46.3 5.5 90 top
UNK2C1  105P/6.3V/1005  [C0402]  71.73 47.98 225 bottom
UNK2C2  222P/16V/1005  [C0402]  66.44 47.52 270 bottom
UNK2C3  150P/50V/1005  [C1005]  78.31 50.98 180 top
UNK2C4  106P/6.3V/1608  [C0603]  61.9 47.88 90 bottom
UNK2C5  104P/16V/1005  [C0402]  73.02 50.32 180 bottom
UNK2C6  106P/6.3V/1608  [C0603]  60.2 47.88 90 bottom
UNK2C7  104P/16V/1005  [C0402]  63.22 47.65 270 bottom
UNK2C8  104P/16V/1005  [C0402]  64.31 47.7 270 bottom
UNK2C9  150P/50V/1005  [C1005]  78.31 52.12 180 top
UNK2C10  105P/6.3V/1005  [C0402]  72.54 46.28 315 bottom
UNK2C11  105P/6.3V/1005  [C0402]  62.91 45.34 90 bottom
UNK2C12  105P/6.3V/1005  [C0402]  75.64 47.07 270 bottom
UNK2C13  106P/6.3V/1608  [C0603]  61.58 44.75 270 bottom
UNK2C14  105P/6.3V/1005  [C0402]  65.38 47.7 270 bottom
UNK2C15  104P/16V/1005  [C1005]  74.1 60.25 0 top
UNK2C16  105P/6.3V/1005  [C0402]  70.15 45.82 0 bottom
UNK2C17  106P/6.3V/1608  [C0603]  77.04 46.66 90 bottom
UNK2C19  104P/16V/1005  [C0402]  67.71 47.52 270 bottom
UNK2C20  105P/6.3V/1005  [C0402]  67.59 45.85 180 bottom
UNK2C22  104P/16V/1005  [C0402]  65.81 51.13 0 bottom
UNK2CON1  OPEN-HB11041  [HDR_4P]  61.35 71.5 0 top
UNK2D3  SZESD7371HT1G  [SOD-323_SZESD7371HT1G]  62.7 65.21 180 top
UNK2D4  SZESD7371HT1G  [SOD-323_SZESD7371HT1G]  69.1 65.21 0 top
UNK2D7  OPEN-BL-HG036A-AV-TRB  [LED1608]  62.5 62.2 90 top
UNK2Q1  OPEN-MMBT3904  [SOT23_LRT_MMBT3904]  66.7 62.4 180 top
UNK2R1  241/1005  [R1005]  66.46 65.21 270 top
UNK2R2  OPEN-103/1005  [R0402]  63.75 50.39 0 bottom
UNK2R3  753/F/1005  [R0402]  76.3 52.73 90 bottom
UNK2R5  474/F/1005  [R1005]  76.68 51.51 90 top
UNK2R8  OPEN-473/1005  [R1005]  69.8 63.5 0 top
UNK2R10  220/F/1005  [R1005]  77.9 53.21 180 top
UNK2R12  OPEN-241/F/1005  [R1005]  64.3 62.4 270 top
UNK2R14  OPEN-104/1005  [R1005]  72.69 55.47 0 top
UNK2R15  243/F/1005  [R0402]  76.81 51.1 180 bottom
UNK2R16  241/1005  [R1005]  65.34 65.21 270 top
UNK2R18  152/1005  [R1005]  55.8 58.8 0 bottom
UNK2R19  152/1005  [R1005]  55.8 55.5 0 bottom
UNK2R24  152/1005  [R1005]  80.4 59.05 0 top
UNK2R27  000/1005  [TEST_R]  71.45 46.96 180 bottom
UNK2R28  152/1005  [R1005]  80.4 57.95 0 top
UNK2R29  472/1005  [R1005]  77.75 49.05 0 bottom
UNK2T3  T_POINT_R_1  [TP0_8PI]  61.7 50.6 270 top
UNK2T5  T_POINT_R_1  [TP0_8PI]  76.71 58.72 0 top
UNK2T6  T_POINT_R_1  [TP0_8PI]  74.78 53.85 0 top
UNK2T7  T_POINT_R_1  [TP0_8PI]  76.71 60.1 0 top
UNK2T8  T_POINT_R_1  [TP0_8PI]  78.03 58.72 0 top
UNK2T15  T_POINT_R_1  [TP1_0PI]  44.5 63.6 270 bottom
UNK2T16  T_POINT_R_1  [TP1_0PI]  44.5 61.6 270 bottom
UNK2T17  T_POINT_R_1  [TP1_0PI]  46.5 63.6 270 bottom
UNK2T18  T_POINT_R_1  [TP1_0PI]  46.5 61.6 270 bottom
UNK2T19  T_POINT_R_1  [TP1_0PI]  48.5 63.6 270 bottom
UNK2T20  T_POINT_R_1  [TP1_0PI]  48.5 61.6 270 bottom
UNK2T21  T_POINT_R_1  [TP1_0PI]  50.5 63.6 270 bottom
UNK2T22  T_POINT_R_1  [TP1_0PI]  50.5 61.6 270 bottom
UNK2T23  T_POINT_R_1  [TP1_0PI]  52.5 63.6 270 bottom
UNK2T24  T_POINT_R_1  [TP1_0PI]  52.5 61.6 270 bottom
UNK2T25  T_POINT_R_1  [TP1_0PI]  54.5 63.6 270 bottom
UNK2T26  T_POINT_R_1  [TP1_0PI]  54.5 61.6 270 bottom
UNK2T27  T_POINT_R_1  [TP1_0PI]  56.5 63.6 270 bottom
UNK2T28  T_POINT_R_1  [TP1_0PI]  56.5 61.6 270 bottom
UNK2T29  T_POINT_R_1  [TP0_8PI]  70.2 54.15 180 bottom
UNK2U2  DIO6809RST3  [SOT23_LRT_DIO6809RST3]  73.63 57.88 270 top
UNK2Y2  24MHz_CL12PF_3225  [XTAL3225]  81.56 52.04 0 top
UNK3C1  105P/6.3V/1005  [C0402]  74.6 46.66 270 bottom
UNK3C2  105P/6.3V/1005  [C0402]  62.52 32.25 270 bottom
UNK3C4  104P/16V/1005  [C0402]  71.55 43.31 180 bottom
UNK3C5  105P/6.3V/1005  [C0402]  68.48 44.27 270 bottom
UNK3C6  106P/6.3V/1608  [C0603]  64.15 25.43 90 bottom
UNK3C7  2R2P/50V/1005  [C0402]  70.71 38.07 225 top
UNK3C8  106P/6.3V/1608  [C0603]  67.28 31.09 90 bottom
UNK3C9  104P/16V/1005  [C0402]  63.45 35.31 0 bottom
UNK3C10  104P/16V/1005  [C0402]  65.56 35.31 180 bottom
UNK3C11  104P/16V/1005  [C0402]  64.5 31.85 0 bottom
UNK3C12  105P/6.3V/1005  [C0402]  70.15 23.7 90 bottom
UNK3C18  105P/6.3V/1005  [C0402]  62.47 26.01 270 bottom
UNK3C19  105P/6.3V/1005  [C0402]  63.88 30.21 270 bottom
UNK3C20  104P/16V/1005  [C0402]  69.52 36.02 180 bottom
UNK3C21  105P/6.3V/1005  [C0402]  63.66 33.69 270 bottom
UNK3C26  106P/6.3V/1608  [C0603]  65.2 29.74 90 bottom
UNK3C27  104P/16V/1005  [C0402]  62.49 30.19 270 bottom
UNK3C28  106P/6.3V/1608  [C0603]  62.61 40.31 135 bottom
UNK3C30  102P/50V/1005  [C0402]  71.22 25.12 90 bottom
UNK3C31  104P/16V/1005  [C0402]  64.36 42.21 315 bottom
UNK3C35  105P/6.3V/1005  [C0402]  62.47 23.93 270 bottom
UNK3C38  105P/6.3V/1005  [C0402]  69.29 32.85 0 bottom
UNK3C39  104P/16V/1005  [C0402]  67.03 43.87 270 bottom
UNK3C40  104P/16V/1005  [C0402]  67.6 25.9 0 bottom
UNK3C42  104P/16V/1005  [C0402]  69.3 33.96 0 bottom
UNK3C45  104P/16V/1005  [C0402]  69.59 29.62 0 bottom
UNK3C46  105P/6.3V/1005  [C0402]  64.18 22.05 0 bottom
UNK3C58  101P/50V/1005  [C0402]  70.86 34.34 270 bottom
UNK3C62  105P/6.3V/1005  [C0402]  65.29 43.01 315 bottom
UNK3R2  OPEN-151/1005  [R0402]  67.24 28.52 270 bottom
UNK3R6  241/F/1005  [R0402]  69.59 43.99 270 bottom
UNK3R8  OPEN-103/1005  [R0402]  64.23 23.37 180 bottom
UNK3R10  241/F/1005  [R0402]  70.99 27.37 180 bottom
UNK3R19  102/F/1005  [R0402]  61.39 28.05 270 bottom
UNK3R20  102/F/1005  [R0402]  61.39 30.19 270 bottom
UNK3T1  T_POINT_R_1  [TP12]  70.47 43.29 180 bottom
UNK3U1  H5TC4G63CFR-RDC  [BGA96_H5TC4G63CFR-RDC]  66.95 29.13 0 top
UNK4C2  105P/6.3V/1005  [C0402]  64.15 44.7 270 bottom
UNK4C3  OPEN-6R8P/50V/1005  [C1005]  58.93 43.79 0 top
UNK4C4  104P/16V/1005  [C1005]  55.7 29.7 0 top
UNK4C5  475P/6.3V/1608  [C1608]  45.35 29.3 0 top
UNK4C8  104P/16V/1005  [C1005]  49.3 51.85 90 bottom
UNK4C9  104P/16V/1005  [C1005]  54.1 31.1 180 bottom
UNK4C10  104P/16V/1005  [C1005]  52.04 53.62 180 top
UNK4C11  104P/16V/1005  [C1005]  55.25 52.75 180 top
UNK4C17  OPEN-104P/16V/1005  [C1005]  50.7 42.1 180 bottom
UNK4C18  OPEN-105P/6.3V/1005  [C1005]  52.15 40.35 180 bottom
UNK4C26  OPEN-105P/6.3V/1005  [C1005]  46.45 42.4 90 bottom
UNK4C34  OPEN-104P/16V/1005  [C1005]  50.7 43.2 180 bottom
UNK4C35  OPEN-105P/6.3V/1005  [C1005]  49.65 37.4 270 bottom
UNK4C47  OPEN-475P/6.3V/1608  [C1608]  50.9 37.65 90 bottom
UNK4C48  104P/16V/1005  [C1005]  45.65 51.35 90 bottom
UNK4C49  104P/16V/1005  [C1005]  50.5 29.7 180 bottom
UNK4K2  TS-1187-1716  [SW_TS-1187]  10.97 14.94 0 top
UNK4R1  OPEN-103/1005  [R1005]  48.65 35.55 90 bottom
UNK4R2  OPEN-472/1005  [R1005]  44.12 54.03 270 top
UNK4R3  000/1005  [R1005]  48.99 54.03 270 top
UNK4R4  473/1005  [R1005]  52.2 31.1 0 bottom
UNK4R5  OPEN-000/1005  [R1005]  52.4 36.5 270 bottom
UNK4R6  000/1005  [R1005]  53.5 36.5 270 bottom
UNK4R7  000/1005  [R1005]  51.15 53.5 180 bottom
UNK4R8  OPEN-000/1005  [R1005]  50.21 54.03 270 top
UNK4R9  OPEN-103/1005  [R1005]  45.3 41.35 90 bottom
UNK4R10  472/1005  [R1005]  46.56 54.03 270 top
UNK4R11  OPEN-000/1005  [R1005]  61.36 43.79 0 top
UNK4R12  103/1005  [R1005]  45.75 39.8 0 bottom
UNK4R13  OPEN-472/1005  [R1005]  45.34 54.03 270 top
UNK4R14  OPEN-472/1005  [R1005]  47.55 35.55 270 bottom
UNK4R15  OPEN-000/1005  [R1005]  60.15 40.5 0 top
UNK4R16  OPEN-472/1005  [R1005]  50.9 44.7 90 bottom
UNK4R17  OPEN-000/1005  [R1005]  46.8 40.9 0 bottom
UNK4R18  OPEN-000/1005  [R1005]  60.15 41.6 0 top
UNK4R19  OPEN-000/1005  [R1005]  61.39 49.05 0 top
UNK4R20  OPEN-000/1005  [R1005]  58.95 49.05 0 top
UNK4R21  OPEN-000/1005  [R1005]  61.39 47.83 0 top
UNK4R22  OPEN-000/1005  [R1005]  58.95 47.83 0 top
UNK4R23  OPEN-000/1005  [R1005]  61.39 46.61 0 top
UNK4R24  OPEN-000/1005  [R1005]  58.95 46.61 0 top
UNK4R25  OPEN-000/1005  [R1005]  61.39 45.39 0 top
UNK4R26  OPEN-000/1005  [R1005]  58.95 45.39 0 top
UNK4R52  OPEN-472/1005  [R1005]  47.78 54.03 270 top
UNK4T25  T_POINT_R_1  [TP0_8PI]  59.55 40.75 180 bottom
UNK4U5  MX30LF4G28AD_TI  [TSOP48_W20_MX30LF4G28AD-TI]  50.39 41.35 90 top
UNK4U9  OPEN-S40FC004C181C  [BGA153_S40FC004C181C]  50.26 41.35 0 top
UNK5C3  105P/6.3V/1005  [C1005]  81.1 42.55 180 top
UNK5C9  104P/16V/1005  [C0402]  71.83 44.93 90 bottom
UNK5C10  104P/16V/1005  [C0402]  74.8 44.98 180 bottom
UNK5C11  105P/6.3V/1005  [C1005]  78.9 43.4 0 top
UNK5C13  104P/16V/1005  [C1005]  103.2 7 180 bottom
UNK5D11  SZESD7371HT1G  [SOD-323_SZESD7371HT1G]  90.25 15.55 90 bottom
UNK5D12  SZESD7371HT1G  [SOD-323_SZESD7371HT1G]  92.05 15.55 90 bottom
UNK5R5  102/1005  [R1005]  79.35 41.85 90 top
UNK5R20  OPEN-103/1005  [R1005]  81.8 40.25 180 bottom
UNK5R64  201/F/1005  [R0402]  77.7 44.55 0 bottom
UNK5R65  BLM15PD121SN1D  [BLM15]  87.4 11.7 90 bottom
UNK5R66  BLM15PD121SN1D  [BLM15]  87.4 14.6 90 bottom
UNK5R67  BLM15PD121SN1D  [BLM15]  86.2 11.7 90 bottom
UNK5R68  BLM15PD121SN1D  [BLM15]  85 11.7 90 bottom
UNK5R69  BLM15PD121SN1D  [BLM15]  84.6 14.2 90 bottom
UNK5R70  OPEN-330/1005  [R1005]  83.65 11.75 90 bottom
UNK5R71  BLM15PD121SN1D  [BLM15]  92.1 11.7 90 bottom
UNK5R72  BLM15PD121SN1D  [BLM15]  91 11.7 90 bottom
UNK5R73  BLM15PD121SN1D  [BLM15]  89.6 11.7 90 bottom
UNK5R74  BLM15PD121SN1D  [BLM15]  88.5 11.7 90 bottom
UNK5R75  BLM15PD121SN1D  [BLM15]  88.5 14.6 90 bottom
UNK5R76  OPEN-101/1005  [R1005]  87.4 17.15 90 bottom
UNK5R77  OPEN-101/1005  [R1005]  88.5 17.15 90 bottom
UNK5R78  OPEN-103/1005  [R1005]  81.1 41.45 0 top
UNK5R83  102/1005  [R1005]  89.15 18.2 180 top
UNK5R84  5R1/F/1005  [R1005]  92.25 16.15 180 top
UNK5R85  5R1/F/1005  [R1005]  92.25 17.35 180 top

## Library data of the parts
C1-C4 C21 C22 C30 C76-C79 C201 C203 C206 C207 C209 C211 C213 C214 C216 C218 C219 C221 C224 C228-C231 C233 C235 C237 C238 C240 C242 C243 C245 C248 C249 C255-C270 C301 C303 C306 C307 C309 C311 C313 C314 C316 C318 C319 C321 C324 C328-C331 C333 C335 C337 C338 C340 C342 C343 C345 C348 C353-C368 UNK2C4 UNK2C6 UNK2C13 UNK2C17 UNK3C6 UNK3C8 UNK3C26 UNK3C28 UNK4C5 UNK4C47 = MLCC 1608_0
C5 C9-C12 C14 C15 C17 C19 C20 C23 C52 C53 C55 C58 C59 C61 C63-C67 C69 C70 C72 C74 C75 C101-C106 C202 C204 C208 C210 C215 C217 C220 C222 C225 C226 C232 C234 C239 C241 C244 C246 C250-C254 C302 C304 C308 C310 C315 C317 C320 C322 C325 C326 C332 C334 C339 C341 C344 C346 C349-C352 UNK2C1-UNK2C3 UNK2C5 UNK2C7-UNK2C12 UNK2C14-UNK2C16 UNK2C19 UNK2C20 UNK2C22 UNK3C1 UNK3C2 UNK3C4 UNK3C5 UNK3C7 UNK3C9-UNK3C12 UNK3C18-UNK3C21 UNK3C27 UNK3C30 UNK3C31 UNK3C35 UNK3C38-UNK3C40 UNK3C42 UNK3C45 UNK3C46 UNK3C58 UNK3C62 UNK4C2-UNK4C4 UNK4C8-UNK4C11 UNK4C17 UNK4C18 UNK4C26 UNK4C34 UNK4C35 UNK4C48 UNK4C49 UNK5C3 UNK5C9-UNK5C11 UNK5C13 = MLCC 1005_0
C6-C8 C13 C16 C18 C51 C54 C56 C57 C60 C62 C68 C71 C73 = MLCC 2012_0
C205 C223 C305 C323 = ECAP-2.5X6.3-D
FB201-FB204 FB301-FB304 = BEAD
J803 J804 = CON4
J812 = CON HEADER 1X4_1
J813 = CON15X1-4G_0
J814 = JP_USB-0400ASMT_0
L1 L2 L51-L53 L201-L204 L211-L214 L301-L304 L311-L314 = INDUCTOR CHIP_0
Q1 = P-MOSFET
Q2-Q5 UNK2Q1 = npn
R1-R3 R6-R13 R15-R20 R51-R63 R101-R110 R201-R217 R219-R231 R233-R236 R238-R240 R301-R317 R319-R344 R348-R351 UNK1R1 UNK1R2 UNK2R1-UNK2R3 UNK2R5 UNK2R8 UNK2R10 UNK2R12 UNK2R14-UNK2R16 UNK2R18 UNK2R19 UNK2R24 UNK2R27-UNK2R29 UNK3R2 UNK3R6 UNK3R8 UNK3R10 UNK3R19 UNK3R20 UNK4R1-UNK4R26 UNK4R52 UNK5R5 UNK5R20 UNK5R64-UNK5R70 UNK5R73-UNK5R78 UNK5R83 = RES-V
T1 = FILTER EMI DLW21SN900SQ2_0
T101-T116 T120 T125-T127 T129 T201-T204 T301-T331 UNK2T3 UNK2T5-UNK2T8 UNK2T15-UNK2T29 UNK3T1 UNK4T25 = T_POINT_R_1
U1 = A113X_20170516_V17
U2 = MP2338GTL
U3 U51-U53 = SY81XX
U54 U55 = WL2003E
U201 U202 U301 U302 = WA20-6829B_0
UNK2CON1 = CN-4P_0
UNK2D3 UNK2D4 UNK5D11 UNK5D12 = TVS DIODE
UNK2D7 = LED_3
UNK2U2 = MAX809RD
UNK2Y2 = SMD_CRYSTAL
UNK3U1 = DDR3_96P_16b_0
UNK4K2 = BUTTON_0
UNK4U5 = NAND-ALL_11
UNK4U9 = eMMC_V5_0.1
UNK5R71 UNK5R72 UNK5R84 UNK5R85 = RES-V: signal model: RES-V_R1005_5R1/F/1005_5R1/F/1005

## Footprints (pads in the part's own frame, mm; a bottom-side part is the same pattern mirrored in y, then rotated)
51318-0023L-001
  round 2.8 hole 1.8: 1(1.98,-7.2) 2(-1.98,-7.2)
A113X
  round 0.3 smd: A1(-5.2,5.2) A2(-4.55,5.2) A3(-3.9,5.2) A4(-3.25,5.2) A5(-2.6,5.2) A6(-1.95,5.2) A7(-1.3,5.2) A8(-0.65,5.2) A9(0,5.2) A10(0.65,5.2) A11(1.3,5.2) A12(1.95,5.2) A13(2.6,5.2) A14(3.25,5.2) A15(3.9,5.2) A16(4.55,5.2) A17(5.2,5.2) B1(-5.2,4.55) B2(-4.55,4.55) B3(-3.9,4.55) B4(-3.25,4.55) B5(-2.6,4.55) B6(-1.95,4.55) B7(-1.3,4.55) B8(-0.65,4.55) B9(0,4.55) B10(0.65,4.55) B11(1.3,4.55) B12(1.95,4.55) B13(2.6,4.55) B14(3.25,4.55) B15(3.9,4.55) B16(4.55,4.55) B17(5.2,4.55) C1(-5.2,3.9) C2(-4.55,3.9) C3(-3.9,3.9) C4(-3.25,3.9) C5(-2.6,3.9) C6(-1.95,3.9) C7(-1.3,3.9) C8(-0.65,3.9) C9(0,3.9) C10(0.65,3.9) C11(1.3,3.9) C12(1.95,3.9) C13(2.6,3.9) C15(3.9,3.9) C16(4.55,3.9) C17(5.2,3.9) D1(-5.2,3.25) D2(-4.55,3.25) D3(-3.9,3.25) D4(-3.25,3.25) D5(-2.6,3.25) D6(-1.95,3.25) D7(-1.3,3.25) D8(-0.65,3.25) D9(0,3.25) D10(0.65,3.25) D11(1.3,3.25) D12(1.95,3.25) D13(2.6,3.25) D14(3.25,3.25) D15(3.9,3.25) D16(4.55,3.25) D17(5.2,3.25) E2(-4.55,2.6) E3(-3.9,2.6) E4(-3.25,2.6) E5(-2.6,2.6) E6(-1.95,2.6) E7(-1.3,2.6) E8(-0.65,2.6) E9(0,2.6) E10(0.65,2.6) E11(1.3,2.6) E12(1.95,2.6) E13(2.6,2.6) E14(3.25,2.6) E15(3.9,2.6) E16(4.55,2.6) E17(5.2,2.6) F1(-5.2,1.95) F2(-4.55,1.95) F3(-3.9,1.95) F4(-3.25,1.95) F5(-2.6,1.95) F6(-1.95,1.95) F7(-1.3,1.95) F8(-0.65,1.95) F9(0,1.95) F10(0.65,1.95) F11(1.3,1.95) F12(1.95,1.95) F13(2.6,1.95) F14(3.25,1.95) F15(3.9,1.95) F16(4.55,1.95) F17(5.2,1.95) G1(-5.2,1.3) G2(-4.55,1.3) G3(-3.9,1.3) G4(-3.25,1.3) G5(-2.6,1.3) G6(-1.95,1.3) G7(-1.3,1.3) G8(-0.65,1.3) G9(0,1.3) G10(0.65,1.3) G11(1.3,1.3) G12(1.95,1.3) G13(2.6,1.3) G14(3.25,1.3) G15(3.9,1.3) G16(4.55,1.3) G17(5.2,1.3) H1(-5.2,0.65) H2(-4.55,0.65) H3(-3.9,0.65) H4(-3.25,0.65) H5(-2.6,0.65) H6(-1.95,0.65) H7(-1.3,0.65) H8(-0.65,0.65) H9(0,0.65) H10(0.65,0.65) H11(1.3,0.65) H12(1.95,0.65) H13(2.6,0.65) H14(3.25,0.65) H15(3.9,0.65) H16(4.55,0.65) H17(5.2,0.65) J1(-5.2,0) J2(-4.55,0) J3(-3.9,0) J4(-3.25,0) J5(-2.6,0) J6(-1.95,0) J7(-1.3,0) J8(-0.65,0) J9(0,0) J10(0.65,0) J11(1.3,0) J12(1.95,0) J13(2.6,0) J14(3.25,0) J15(3.9,0) J16(4.55,0) J17(5.2,0) K1(-5.2,-0.65) K2(-4.55,-0.65) K3(-3.9,-0.65) K4(-3.25,-0.65) K5(-2.6,-0.65) K6(-1.95,-0.65) K7(-1.3,-0.65) K8(-0.65,-0.65) K9(0,-0.65) K10(0.65,-0.65) K11(1.3,-0.65) K12(1.95,-0.65) K13(2.6,-0.65) K14(3.25,-0.65) K15(3.9,-0.65) K16(4.55,-0.65) K17(5.2,-0.65) L1(-5.2,-1.3) L2(-4.55,-1.3) L3(-3.9,-1.3) L4(-3.25,-1.3) L5(-2.6,-1.3) L6(-1.95,-1.3) L7(-1.3,-1.3) L8(-0.65,-1.3) L9(0,-1.3) L11(1.3,-1.3) L12(1.95,-1.3) L13(2.6,-1.3) L14(3.25,-1.3) L15(3.9,-1.3) L16(4.55,-1.3) L17(5.2,-1.3) M1(-5.2,-1.95) M2(-4.55,-1.95) M3(-3.9,-1.95) M4(-3.25,-1.95) M5(-2.6,-1.95) M6(-1.95,-1.95) M7(-1.3,-1.95) M8(-0.65,-1.95) M9(0,-1.95) M10(0.65,-1.95) M11(1.3,-1.95) M12(1.95,-1.95) M13(2.6,-1.95) M14(3.25,-1.95) M15(3.9,-1.95) M16(4.55,-1.95) M17(5.2,-1.95) N1(-5.2,-2.6) N2(-4.55,-2.6) N3(-3.9,-2.6) N4(-3.25,-2.6) N5(-2.6,-2.6) N6(-1.95,-2.6) N7(-1.3,-2.6) N8(-0.65,-2.6) N9(0,-2.6) N10(0.65,-2.6) N11(1.3,-2.6) N12(1.95,-2.6) N13(2.6,-2.6) N14(3.25,-2.6) N15(3.9,-2.6) N16(4.55,-2.6) P1(-5.2,-3.25) P2(-4.55,-3.25) P3(-3.9,-3.25) P4(-3.25,-3.25) P5(-2.6,-3.25) P6(-1.95,-3.25) P7(-1.3,-3.25) P8(-0.65,-3.25) P9(0,-3.25) P10(0.65,-3.25) P11(1.3,-3.25) P12(1.95,-3.25) P13(2.6,-3.25) P14(3.25,-3.25) P15(3.9,-3.25) P16(4.55,-3.25) P17(5.2,-3.25) R1(-5.2,-3.9) R2(-4.55,-3.9) R3(-3.9,-3.9) R4(-3.25,-3.9) R5(-2.6,-3.9) R6(-1.95,-3.9) R7(-1.3,-3.9) R8(-0.65,-3.9) R9(0,-3.9) R10(0.65,-3.9) R11(1.3,-3.9) R12(1.95,-3.9) R13(2.6,-3.9) R14(3.25,-3.9) R15(3.9,-3.9) R16(4.55,-3.9) R17(5.2,-3.9) T1(-5.2,-4.55) T2(-4.55,-4.55) T3(-3.9,-4.55) T4(-3.25,-4.55) T5(-2.6,-4.55) T6(-1.95,-4.55) T7(-1.3,-4.55) T8(-0.65,-4.55) T9(0,-4.55) T10(0.65,-4.55) T11(1.3,-4.55) T12(1.95,-4.55) T13(2.6,-4.55) T14(3.25,-4.55) T15(3.9,-4.55) T16(4.55,-4.55) T17(5.2,-4.55) U1(-5.2,-5.2) U2(-4.55,-5.2) U3(-3.9,-5.2) U4(-3.25,-5.2) U5(-2.6,-5.2) U6(-1.95,-5.2) U7(-1.3,-5.2) U9(0,-5.2) U10(0.65,-5.2) U11(1.3,-5.2) U12(1.95,-5.2) U13(2.6,-5.2) U14(3.25,-5.2) U15(3.9,-5.2) U16(4.55,-5.2) U17(5.2,-5.2)
BGA96_H5TC4G63CFR-RDC
  round 0.4 smd: A1(-3.2,6) A2(-2.4,6) A3(-1.6,6) A7(1.6,6) A8(2.4,6) A9(3.2,6) B1(-3.2,5.2) B2(-2.4,5.2) B3(-1.6,5.2) B7(1.6,5.2) B8(2.4,5.2) B9(3.2,5.2) C1(-3.2,4.4) C2(-2.4,4.4) C3(-1.6,4.4) C7(1.6,4.4) C8(2.4,4.4) C9(3.2,4.4) D1(-3.2,3.6) D2(-2.4,3.6) D3(-1.6,3.6) D7(1.6,3.6) D8(2.4,3.6) D9(3.2,3.6) E1(-3.2,2.8) E2(-2.4,2.8) E3(-1.6,2.8) E7(1.6,2.8) E8(2.4,2.8) E9(3.2,2.8) F1(-3.2,2) F2(-2.4,2) F3(-1.6,2) F7(1.6,2) F8(2.4,2) F9(3.2,2) G1(-3.2,1.2) G2(-2.4,1.2) G3(-1.6,1.2) G7(1.6,1.2) G8(2.4,1.2) G9(3.2,1.2) H1(-3.2,0.4) H2(-2.4,0.4) H3(-1.6,0.4) H7(1.6,0.4) H8(2.4,0.4) H9(3.2,0.4) J1(-3.2,-0.4) J2(-2.4,-0.4) J3(-1.6,-0.4) J7(1.6,-0.4) J8(2.4,-0.4) J9(3.2,-0.4) K1(-3.2,-1.2) K2(-2.4,-1.2) K3(-1.6,-1.2) K7(1.6,-1.2) K8(2.4,-1.2) K9(3.2,-1.2) L1(-3.2,-2) L2(-2.4,-2) L3(-1.6,-2) L7(1.6,-2) L8(2.4,-2) L9(3.2,-2) M1(-3.2,-2.8) M2(-2.4,-2.8) M3(-1.6,-2.8) M7(1.6,-2.8) M8(2.4,-2.8) M9(3.2,-2.8) N1(-3.2,-3.6) N2(-2.4,-3.6) N3(-1.6,-3.6) N7(1.6,-3.6) N8(2.4,-3.6) N9(3.2,-3.6) P1(-3.2,-4.4) P2(-2.4,-4.4) P3(-1.6,-4.4) P7(1.6,-4.4) P8(2.4,-4.4) P9(3.2,-4.4) R1(-3.2,-5.2) R2(-2.4,-5.2) R3(-1.6,-5.2) R7(1.6,-5.2) R8(2.4,-5.2) R9(3.2,-5.2) T1(-3.2,-6) T2(-2.4,-6) T3(-1.6,-6) T7(1.6,-6) T8(2.4,-6) T9(3.2,-6)
BGA153_S40FC004C181C
  round 0.3 smd: A4(-1.75,6.75) A6(-0.75,6.75) A9(0.75,6.75) A11(1.75,6.75) AA1(-3.25,-3.25) AA2(-2.75,-3.25) AA3(-2.25,-3.25) AA4(-1.75,-3.25) AA5(-1.25,-3.25) AA6(-0.75,-3.25) AA7(-0.25,-3.25) AA8(0.25,-3.25) AA9(0.75,-3.25) AA10(1.25,-3.25) AA11(1.75,-3.25) AA12(2.25,-3.25) AA13(2.75,-3.25) AA14(3.25,-3.25) AE1(-3.25,-5.25) AE14(3.25,-5.25) AG2(-2.75,-6.25) AG13(2.75,-6.25) AH4(-1.75,-6.75) AH6(-0.75,-6.75) AH9(0.75,-6.75) AH11(1.75,-6.75) B2(-2.75,6.25) B13(2.75,6.25) D1(-3.25,5.25) D14(3.25,5.25) H1(-3.25,3.25) H2(-2.75,3.25) H3(-2.25,3.25) H4(-1.75,3.25) H5(-1.25,3.25) H6(-0.75,3.25) H7(-0.25,3.25) H8(0.25,3.25) H9(0.75,3.25) H10(1.25,3.25) H11(1.75,3.25) H12(2.25,3.25) H13(2.75,3.25) H14(3.25,3.25) J1(-3.25,2.75) J2(-2.75,2.75) J3(-2.25,2.75) J4(-1.75,2.75) J5(-1.25,2.75) J6(-0.75,2.75) J7(-0.25,2.75) J8(0.25,2.75) J9(0.75,2.75) J10(1.25,2.75) J11(1.75,2.75) J12(2.25,2.75) J13(2.75,2.75) J14(3.25,2.75) K1(-3.25,2.25) K2(-2.75,2.25) K3(-2.25,2.25) K4(-1.75,2.25) K5(-1.25,2.25) K6(-0.75,2.25) K7(-0.25,2.25) K8(0.25,2.25) K9(0.75,2.25) K10(1.25,2.25) K11(1.75,2.25) K12(2.25,2.25) K13(2.75,2.25) K14(3.25,2.25) L1(-3.25,1.75) L2(-2.75,1.75) L3(-2.25,1.75) L4(-1.75,1.75) L12(2.25,1.75) L13(2.75,1.75) L14(3.25,1.75) M1(-3.25,1.25) M2(-2.75,1.25) M3(-2.25,1.25) M5(-1.25,1.25) M6(-0.75,1.25) M7(-0.25,1.25) M8(0.25,1.25) M9(0.75,1.25) M10(1.25,1.25) M12(2.25,1.25) M13(2.75,1.25) M14(3.25,1.25) N1(-3.25,0.75) N2(-2.75,0.75) N3(-2.25,0.75) N5(-1.25,0.75) N10(1.25,0.75) N12(2.25,0.75) N13(2.75,0.75) N14(3.25,0.75) P1(-3.25,0.25) P2(-2.75,0.25) P3(-2.25,0.25) P5(-1.25,0.25) P10(1.25,0.25) P12(2.25,0.25) P13(2.75,0.25) P14(3.25,0.25) R1(-3.25,-0.25) R2(-2.75,-0.25) R3(-2.25,-0.25) R5(-1.25,-0.25) R10(1.25,-0.25) R12(2.25,-0.25) R13(2.75,-0.25) R14(3.25,-0.25) T1(-3.25,-0.75) T2(-2.75,-0.75) T3(-2.25,-0.75) T5(-1.25,-0.75) T10(1.25,-0.75) T12(2.25,-0.75) T13(2.75,-0.75) T14(3.25,-0.75) U1(-3.25,-1.25) U2(-2.75,-1.25) U3(-2.25,-1.25) U5(-1.25,-1.25) U6(-0.75,-1.25) U7(-0.25,-1.25) U8(0.25,-1.25) U9(0.75,-1.25) U10(1.25,-1.25) U12(2.25,-1.25) U13(2.75,-1.25) U14(3.25,-1.25) V1(-3.25,-1.75) V2(-2.75,-1.75) V3(-2.25,-1.75) V12(2.25,-1.75) V13(2.75,-1.75) V14(3.25,-1.75) W1(-3.25,-2.25) W2(-2.75,-2.25) W3(-2.25,-2.25) W4(-1.75,-2.25) W5(-1.25,-2.25) W6(-0.75,-2.25) W7(-0.25,-2.25) W8(0.25,-2.25) W9(0.75,-2.25) W10(1.25,-2.25) W11(1.75,-2.25) W12(2.25,-2.25) W13(2.75,-2.25) W14(3.25,-2.25) Y1(-3.25,-2.75) Y2(-2.75,-2.75) Y3(-2.25,-2.75) Y4(-1.75,-2.75) Y5(-1.25,-2.75) Y6(-0.75,-2.75) Y7(-0.25,-2.75) Y8(0.25,-2.75) Y9(0.75,-2.75) Y10(1.25,-2.75) Y11(1.75,-2.75) Y12(2.25,-2.75) Y13(2.75,-2.75) Y14(3.25,-2.75)
BLM15
  rect 0.5x0.6 smd: 1(-0.4,0) 2(0.4,0)
BLM21
  rect 0.8x1.3 smd: 1(-0.8,0) 2(0.8,0)
C0402
  rect 0.508x0.508 smd: 1(-0.508,0) 2(0.508,0)
C0603
  rect 0.813x0.864 smd: 1(-0.762,0) 2(0.762,0)
C1005
  rect 0.5x0.6 smd: 1(-0.45,0) 2(0.45,0)
C1608
  rect 0.6x0.9 smd: 1(-0.7,0) 2(0.7,0)
C2012
  rect 0.8x1.4 smd: 1(-0.85,0) 2(0.85,0)
C3216
  rect 1x1.7 smd: 1(-1.5,0) 2(1.5,0)
C3225
  rect 1.6x2.7 smd: 1(-1.3,0) 2(1.3,0)
CIS2012
  rect 0.8x1.4 smd: 1(-0.85,0) 2(0.85,0)
COIL_BPPM00121190
  rect 3.6x3.2 smd: 1(-5.1,2.65) 2(-5.1,-2.65) 3(5.1,-2.65) 4(5.1,2.65)
COIL_LVS404018
  rect 4.3x1.7 smd: 1(0,1.45) 2(0,-1.45)
COIL_MLPS5035
  rect 5.4x1.95 smd: 1(0,1.725) 2(0,-1.725)
COIL_SMPI0402BW
  rect 1.5x2.5 smd: 1(-1.85,0) 2(1.85,0)
COIL_SPH10040
  rect 3.1x3.8 smd: 1(-5,0) 2(5,0)
ECAP_8PI_H10
  oval 4.6x2.2 smd: 1(3.35,0) 2(-3.35,0)
FH41-15S-0_5SH
  rect 0.25x0.65 smd: 1(3.5,-3.2) 2(3,-3.2) 3(2.5,-3.2) 4(2,-3.2) 5(1.5,-3.2) 6(1,-3.2) 7(0.5,-3.2) 8(0,-3.2) 9(-0.5,-3.2) 10(-1,-3.2) 11(-1.5,-3.2) 12(-2,-3.2) 13(-2.5,-3.2) 14(-3,-3.2) 15(-3.5,-3.2)
  rect 0.4x1.55 smd: S1(-4.75,2.05) S5(4.75,2.05)
  rect 0.2x1.2 smd: S2(-2.5,2.475) S3(0,2.475) S4(2.5,2.475)
HDR_4P
  round 1.7 hole 1.1: 1(0,0) 2(2.54,0) 3(5.08,0) 4(7.62,0)
LED1608
  rect 0.9x1 smd: 1(-0.75,0) 2(0.75,0)
MICRO_USB_10118192
  rect 0.4x1.35 smd: 1(-1.3,2.325) 2(-0.65,2.325) 3(0,2.325) 4(0.65,2.325) 5(1.3,2.325)
  rect 2.1x1.6 smd: 6(-3.1,2.2) 7(3.1,2.2)
  rect 1.8x1.9 smd: 8(-3.8,-0.35) 9(-1.15,-0.35) 10(1.15,-0.35) 11(3.8,-0.35)
QFN40_P0_5_W6_WA20-6829B
  oval 0.7x0.38 smd: 1(-2.9,2.25) 2(-2.9,1.75) 3(-2.9,1.25) 4(-2.9,0.75) 5(-2.9,0.25) 6(-2.9,-0.25) 7(-2.9,-0.75) 8(-2.9,-1.25) 9(-2.9,-1.75) 10(-2.9,-2.25) 21(2.9,-2.25) 22(2.9,-1.75) 23(2.9,-1.25) 24(2.9,-0.75) 25(2.9,-0.25) 26(2.9,0.25) 27(2.9,0.75) 28(2.9,1.25) 29(2.9,1.75) 30(2.9,2.25)
  oval 0.38x0.7 smd: 11(-2.25,-2.9) 12(-1.75,-2.9) 13(-1.25,-2.9) 14(-0.75,-2.9) 15(-0.25,-2.9) 16(0.25,-2.9) 17(0.75,-2.9) 18(1.25,-2.9) 19(1.75,-2.9) 20(2.25,-2.9) 31(2.25,2.9) 32(1.75,2.9) 33(1.25,2.9) 34(0.75,2.9) 35(0.25,2.9) 36(-0.25,2.9) 37(-0.75,2.9) 38(-1.25,2.9) 39(-1.75,2.9) 40(-2.25,2.9)
  rect 4.6x3.4 smd: 41(0,0)
R0402
  rect 0.508x0.508 smd: 1(-0.508,0) 2(0.508,0)
R1005
  rect 0.5x0.6 smd: 1(-0.45,0) 2(0.45,0)
R1608
  rect 0.6x0.9 smd: 1(-0.7,0) 2(0.7,0)
R2012
  rect 0.8x1.4 smd: 1(-0.85,0) 2(0.85,0)
SOD-323_SZESD7371HT1G
  rect 0.8x0.5 smd: 1(-1.15,0) 2(1.15,0)
SOT23-5_TMI6050
  rect 0.6x0.8 smd: 1(-0.95,-1.3) 2(0,-1.3) 3(0.95,-1.3) 4(0.95,1.3) 5(-0.95,1.3)
SOT23-6P_TMI3252S
  rect 0.65x1 smd: 1(-1.025,-1.3) 3(1.025,-1.3) 4(1.025,1.3) 6(-1.025,1.3)
  rect 0.5x1 smd: 2(0,-1.3) 5(0,1.3)
SOT23_LRT_DIO6809RST3
  rect 0.7x0.7 smd: 1(-0.95,-1.1) 2(0.95,-1.1) 3(0,1.1)
SOT23_LRT_MMBT3904
  rect 0.7x0.7 smd: 1(-0.95,-1.1) 2(0.95,-1.1) 3(0,1.1)
SOT23_LRT_W2_7_WPM3401
  rect 0.7x0.9 smd: 1(-0.95,-1.2) 2(0.95,-1.2) 3(0,1.2)
SOT583_MP2338
  rect 0.25x0.6 smd: 1(-0.75,-0.7) 2(-0.25,-0.7) 3(0.25,-0.7) 4(0.75,-0.7) 5(0.75,0.7) 6(0.25,0.7) 7(-0.25,0.7) 8(-0.75,0.7)
SW_TS-1187
  rect 0.8x0.9 smd: 1(-3,1.85) 2(3,1.85) 3(-3,-1.85) 4(3,-1.85)
SWPA6045S
  rect 5.7x2.1 smd: 1(0,-2.45) 2(0,2.45)
SWPA8065S
  rect 7.5x2.2 smd: 1(0,3) 2(0,-3)
SXB-EH-4P
  round 1.5 hole 1: 1(-3.75,-3.7) 2(-1.25,-3.7) 3(1.25,-3.7) 4(3.75,-3.7)
TEST_R
  rect 0.203x0.203 smd: 1(-0.102,0) 2(0.102,0)
TP0_8PI
  round 0.8 smd: 1(0,0)
TP1_0PI
  round 1 smd: 1(0,0)
TP12
  round 0.3 smd: 1(0,0)
TSOP48_W20_MX30LF4G28AD-TI
  oval 1.6x0.25 smd: 1(-9.8,5.75) 2(-9.8,5.25) 3(-9.8,4.75) 4(-9.8,4.25) 5(-9.8,3.75) 6(-9.8,3.25) 7(-9.8,2.75) 8(-9.8,2.25) 9(-9.8,1.75) 10(-9.8,1.25) 11(-9.8,0.75) 12(-9.8,0.25) 13(-9.8,-0.25) 14(-9.8,-0.75) 15(-9.8,-1.25) 16(-9.8,-1.75) 17(-9.8,-2.25) 18(-9.8,-2.75) 19(-9.8,-3.25) 20(-9.8,-3.75) 21(-9.8,-4.25) 22(-9.8,-4.75) 23(-9.8,-5.25) 24(-9.8,-5.75) 25(9.8,-5.75) 26(9.8,-5.25) 27(9.8,-4.75) 28(9.8,-4.25) 29(9.8,-3.75) 30(9.8,-3.25) 31(9.8,-2.75) 32(9.8,-2.25) 33(9.8,-1.75) 34(9.8,-1.25) 35(9.8,-0.75) 36(9.8,-0.25) 37(9.8,0.25) 38(9.8,0.75) 39(9.8,1.25) 40(9.8,1.75) 41(9.8,2.25) 42(9.8,2.75) 43(9.8,3.25) 44(9.8,3.75) 45(9.8,4.25) 46(9.8,4.75) 47(9.8,5.25) 48(9.8,5.75)
unnamed
  round 0.6 hole 0.6 unplated: (-2.5,0) (2.5,0)
  round 0.5 hole 0.5 unplated: (-1.5,0) (-0.5,0) (0.5,0) (1.5,0)
unnamed#2
  round 7 hole 4.2: 1(0,0)
unnamed#4
  round 0.5 hole 0.5 unplated: (-1,0) (0,0) (1,0)
unnamed#5
  round 2.5 hole 2.5 unplated: (0,0)
XTAL3225
  rect 1.3x1.1 smd: 1(-1.15,-0.875) 2(1.15,-0.875) 3(1.15,0.875) 4(-1.15,0.875)

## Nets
5V_EN: C12.2 R1.1 R2.1 R2.2 R3.2 U2.6(EN) UNK5R73.2
